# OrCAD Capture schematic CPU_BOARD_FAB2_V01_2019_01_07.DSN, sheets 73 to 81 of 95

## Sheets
73 063 SNOWFLAKE_3: size B
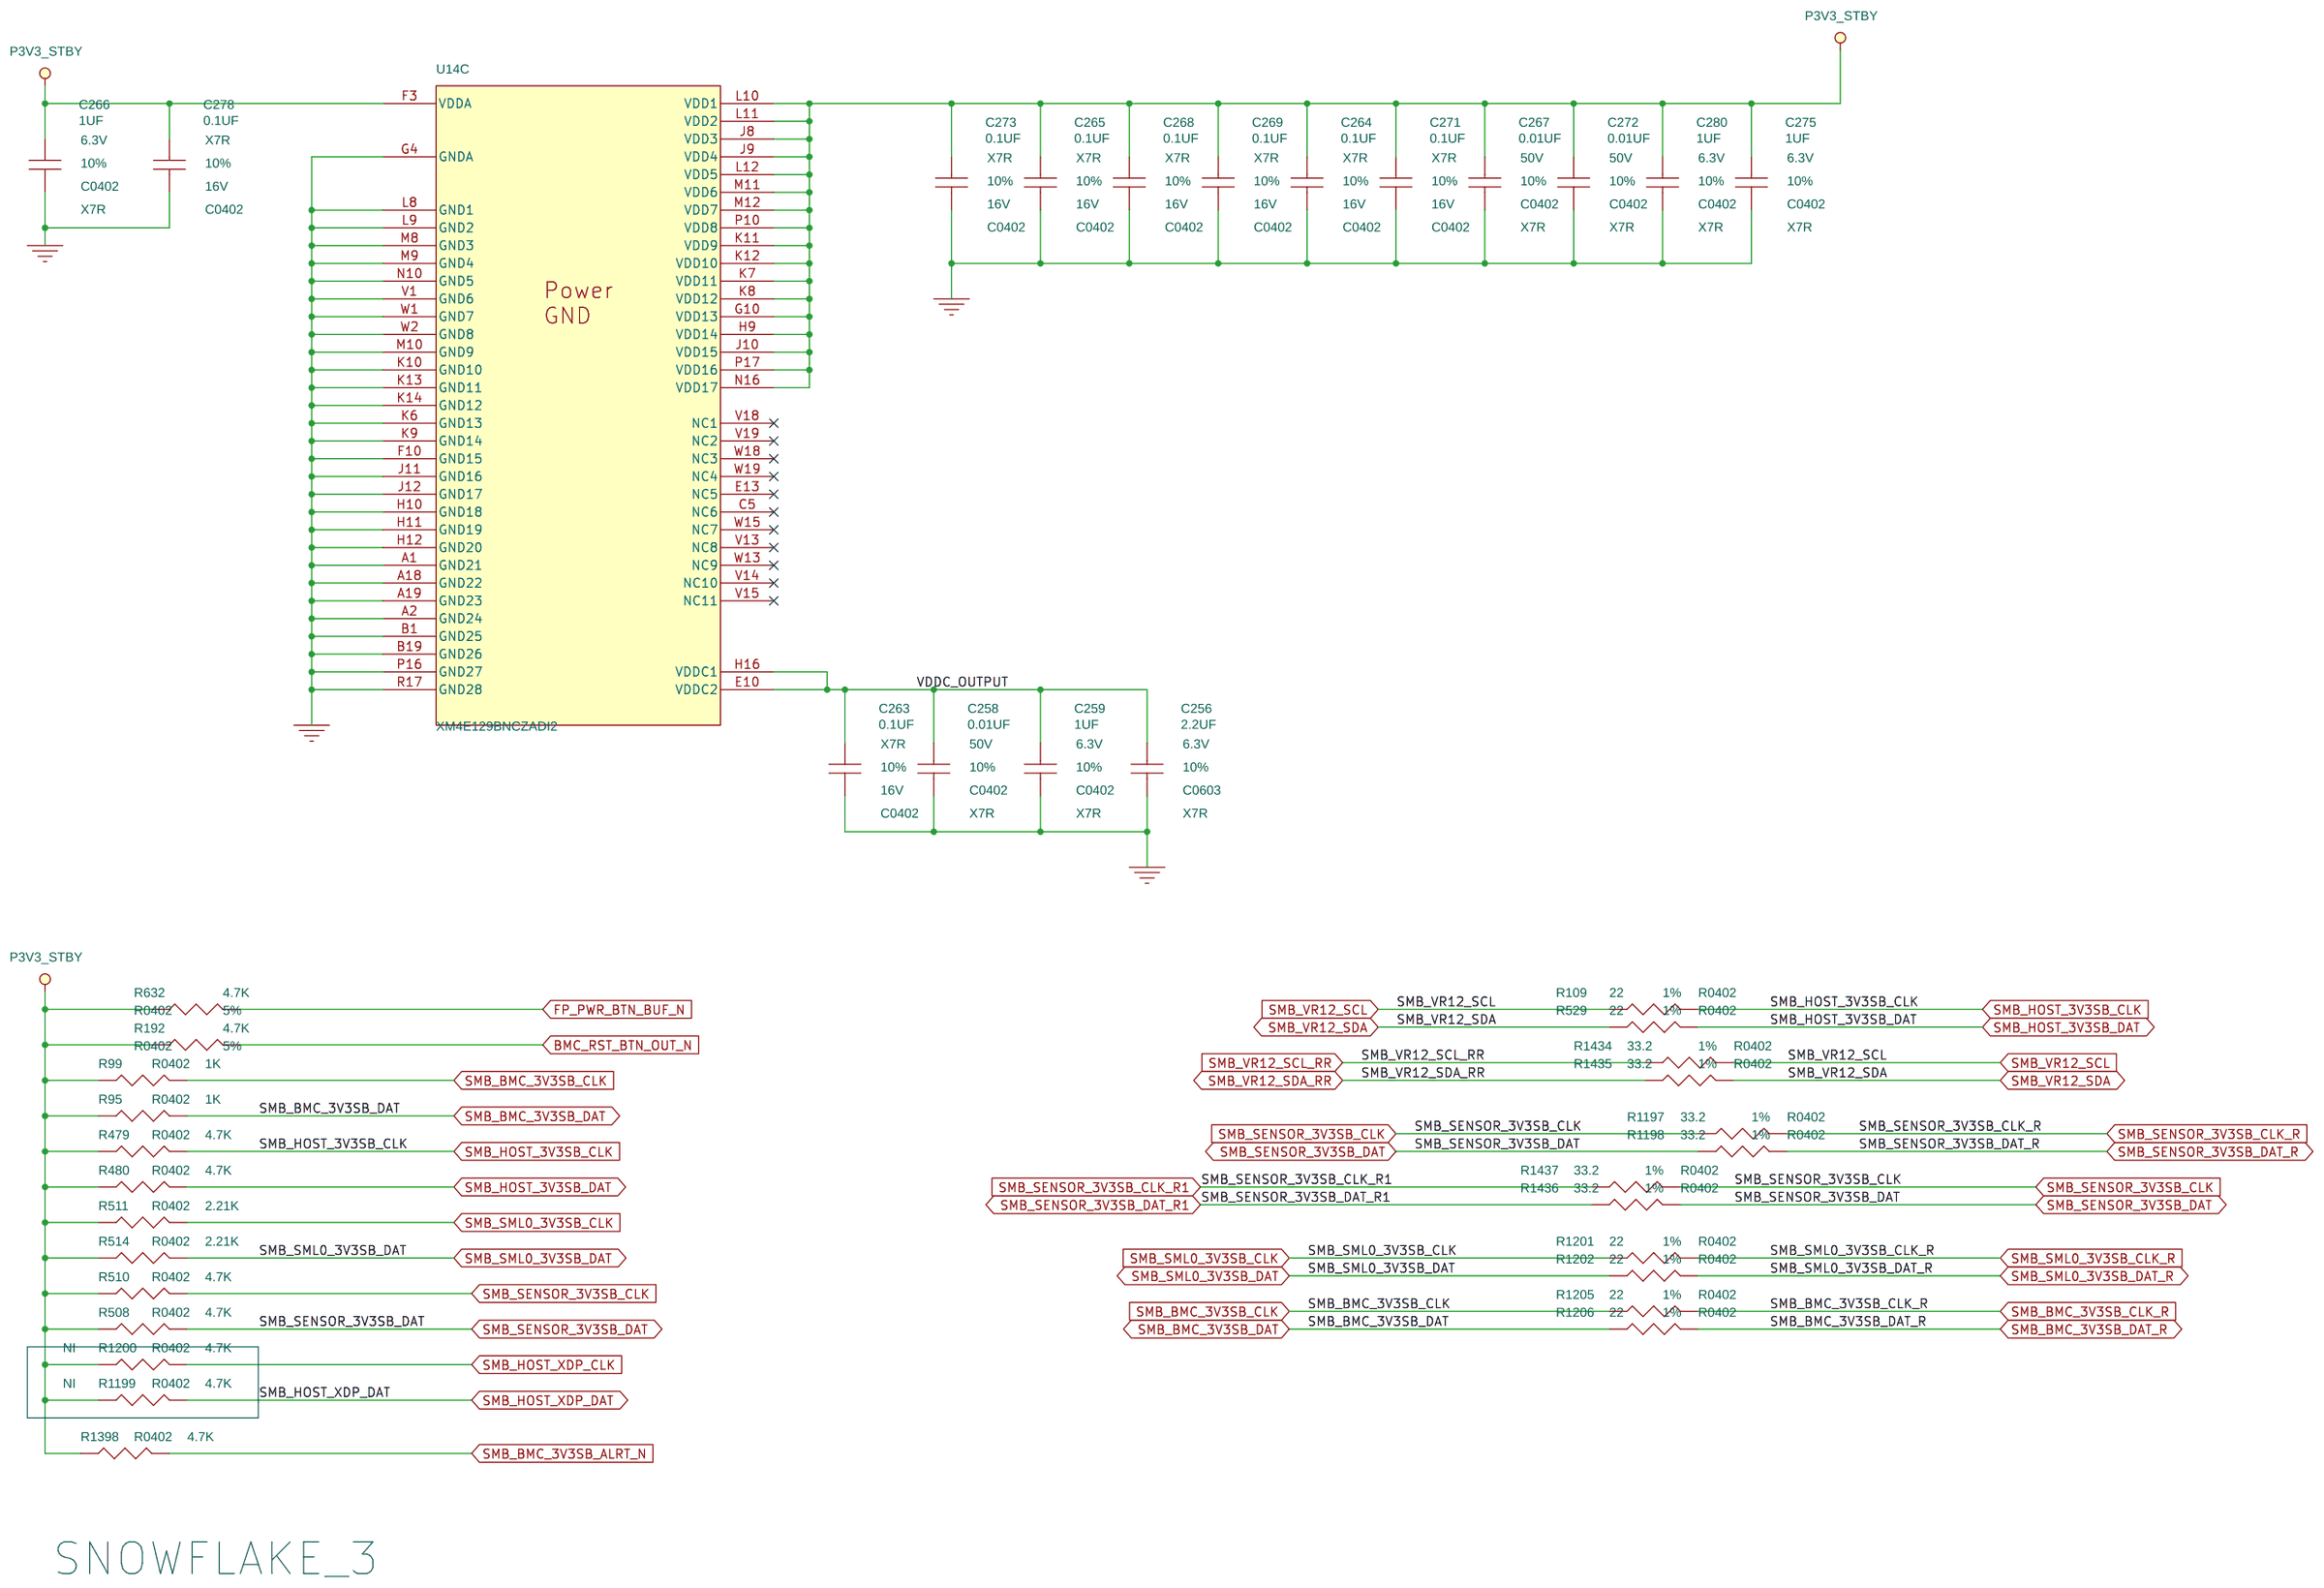
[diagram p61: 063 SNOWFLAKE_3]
74 064 VOLTAGE MONITOR: size B
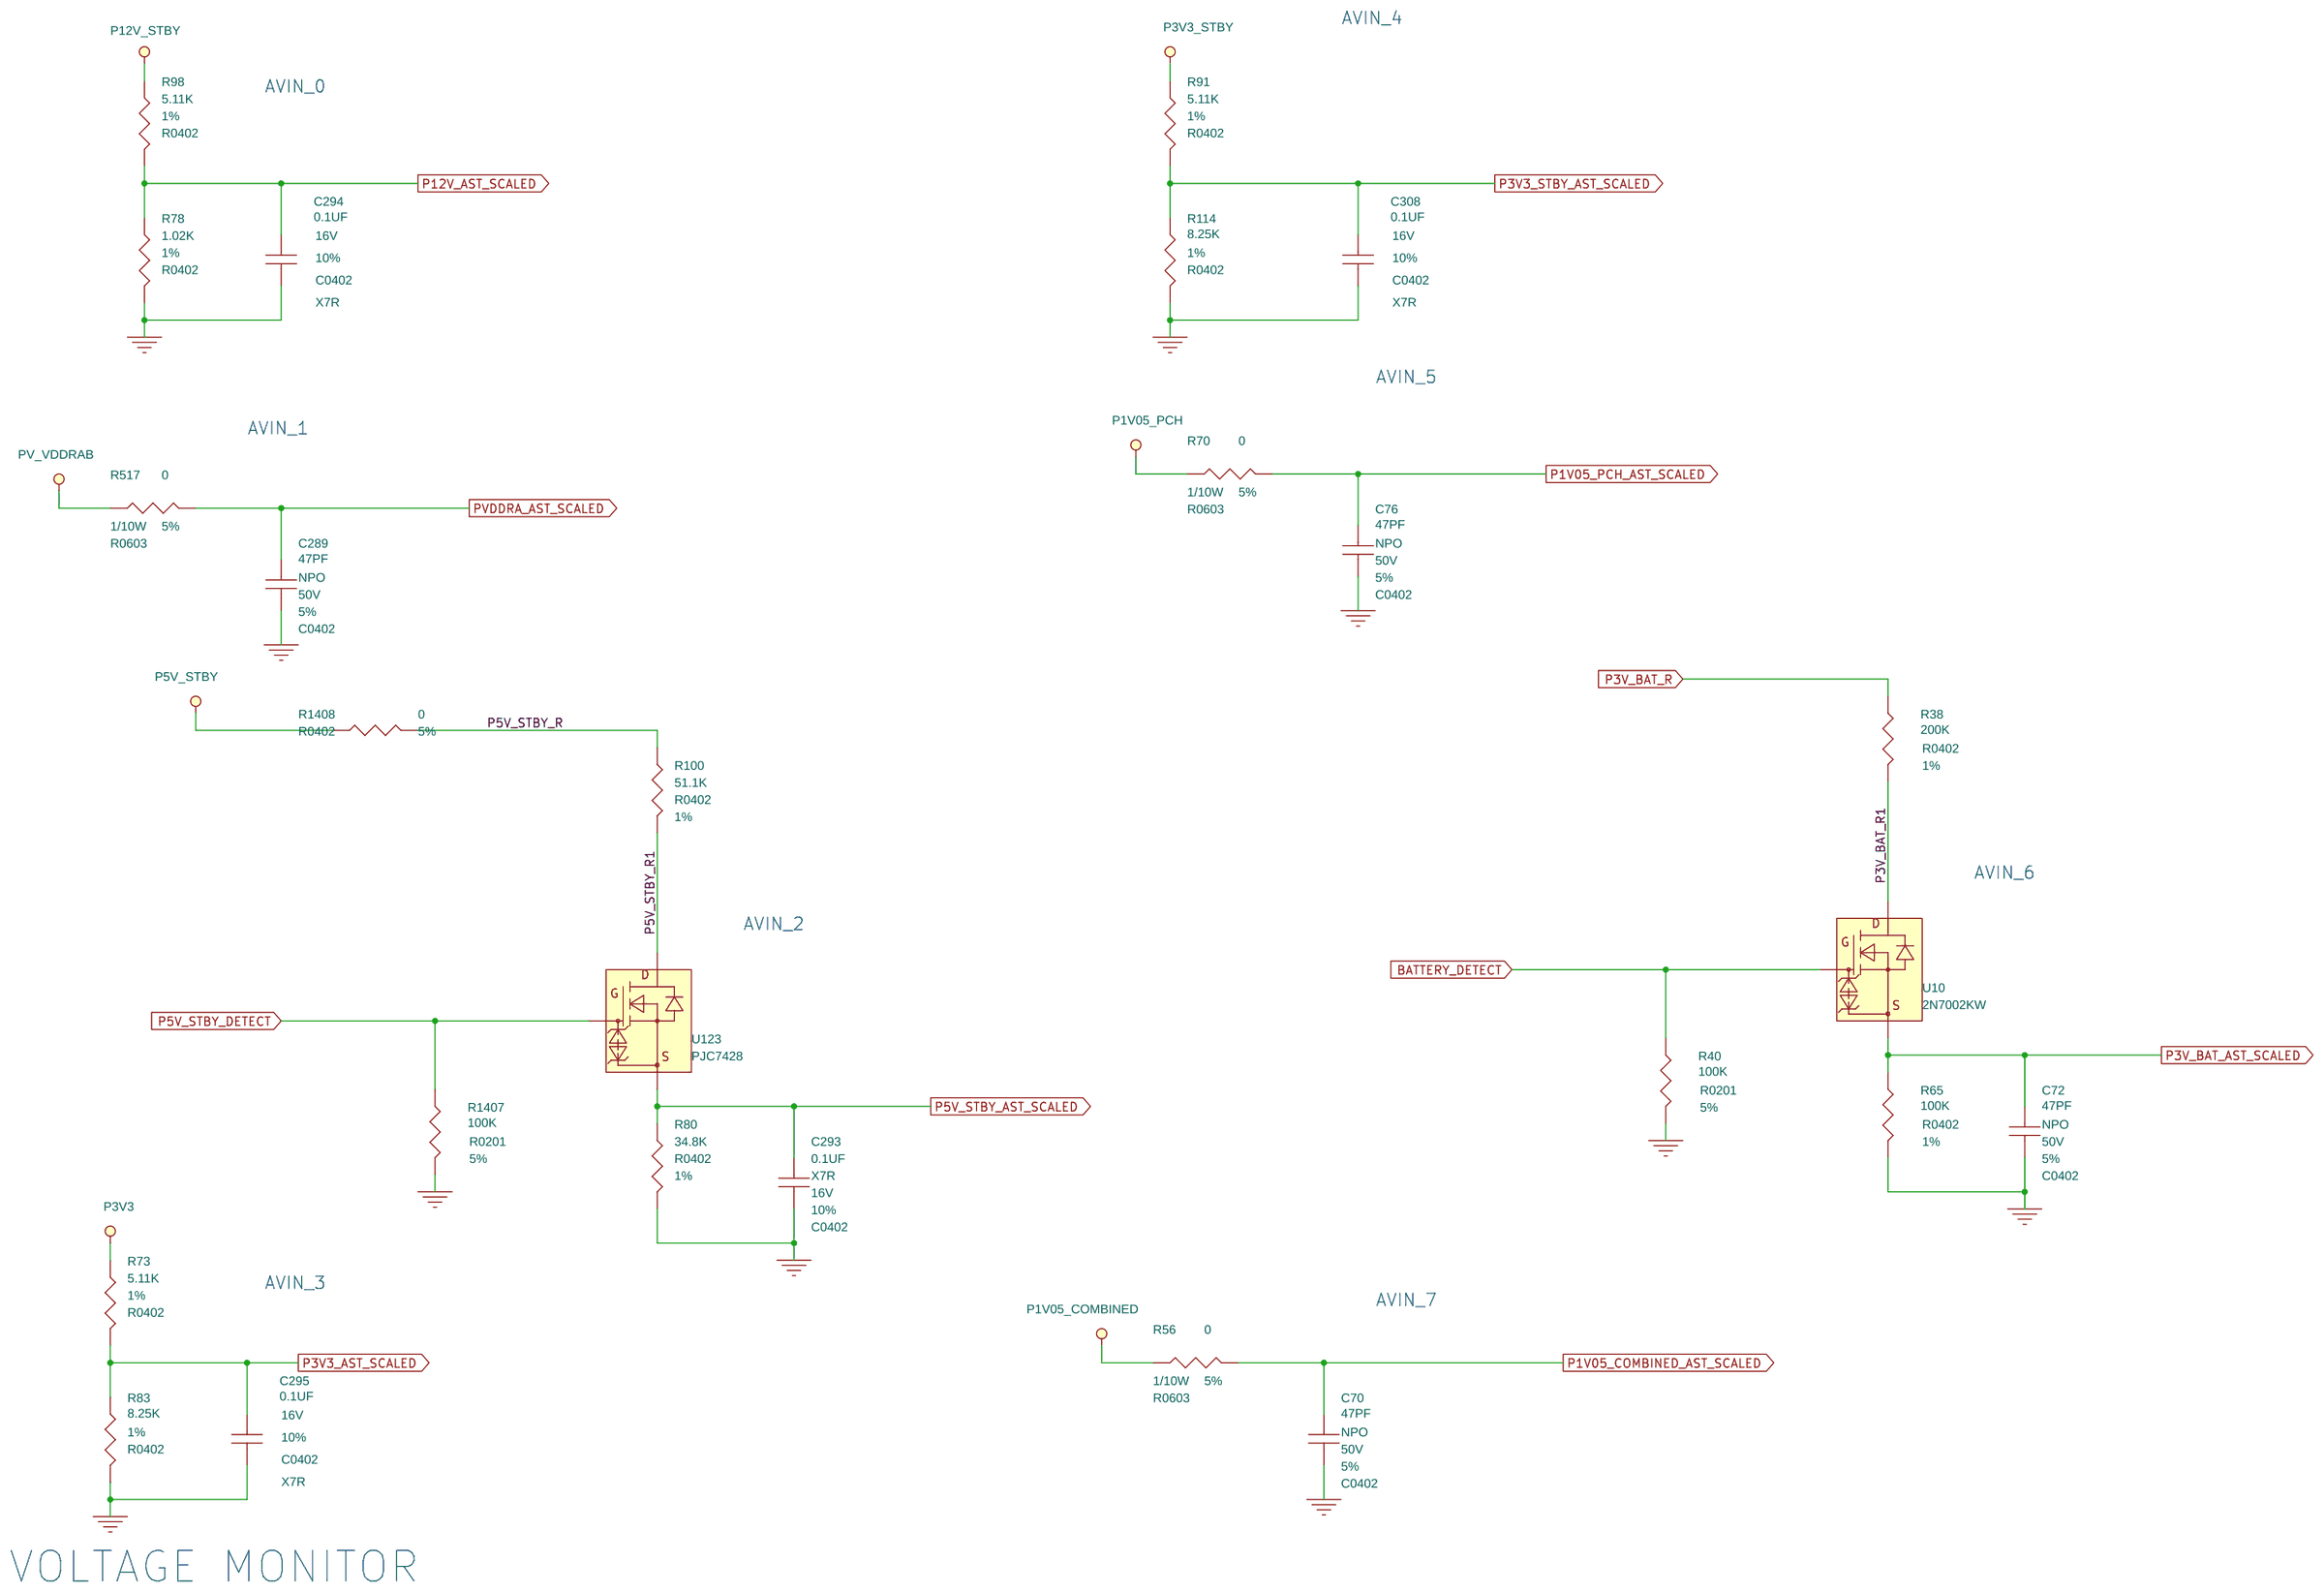
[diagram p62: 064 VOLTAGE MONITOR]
75 065 SMBUS ISOLATOR: size B
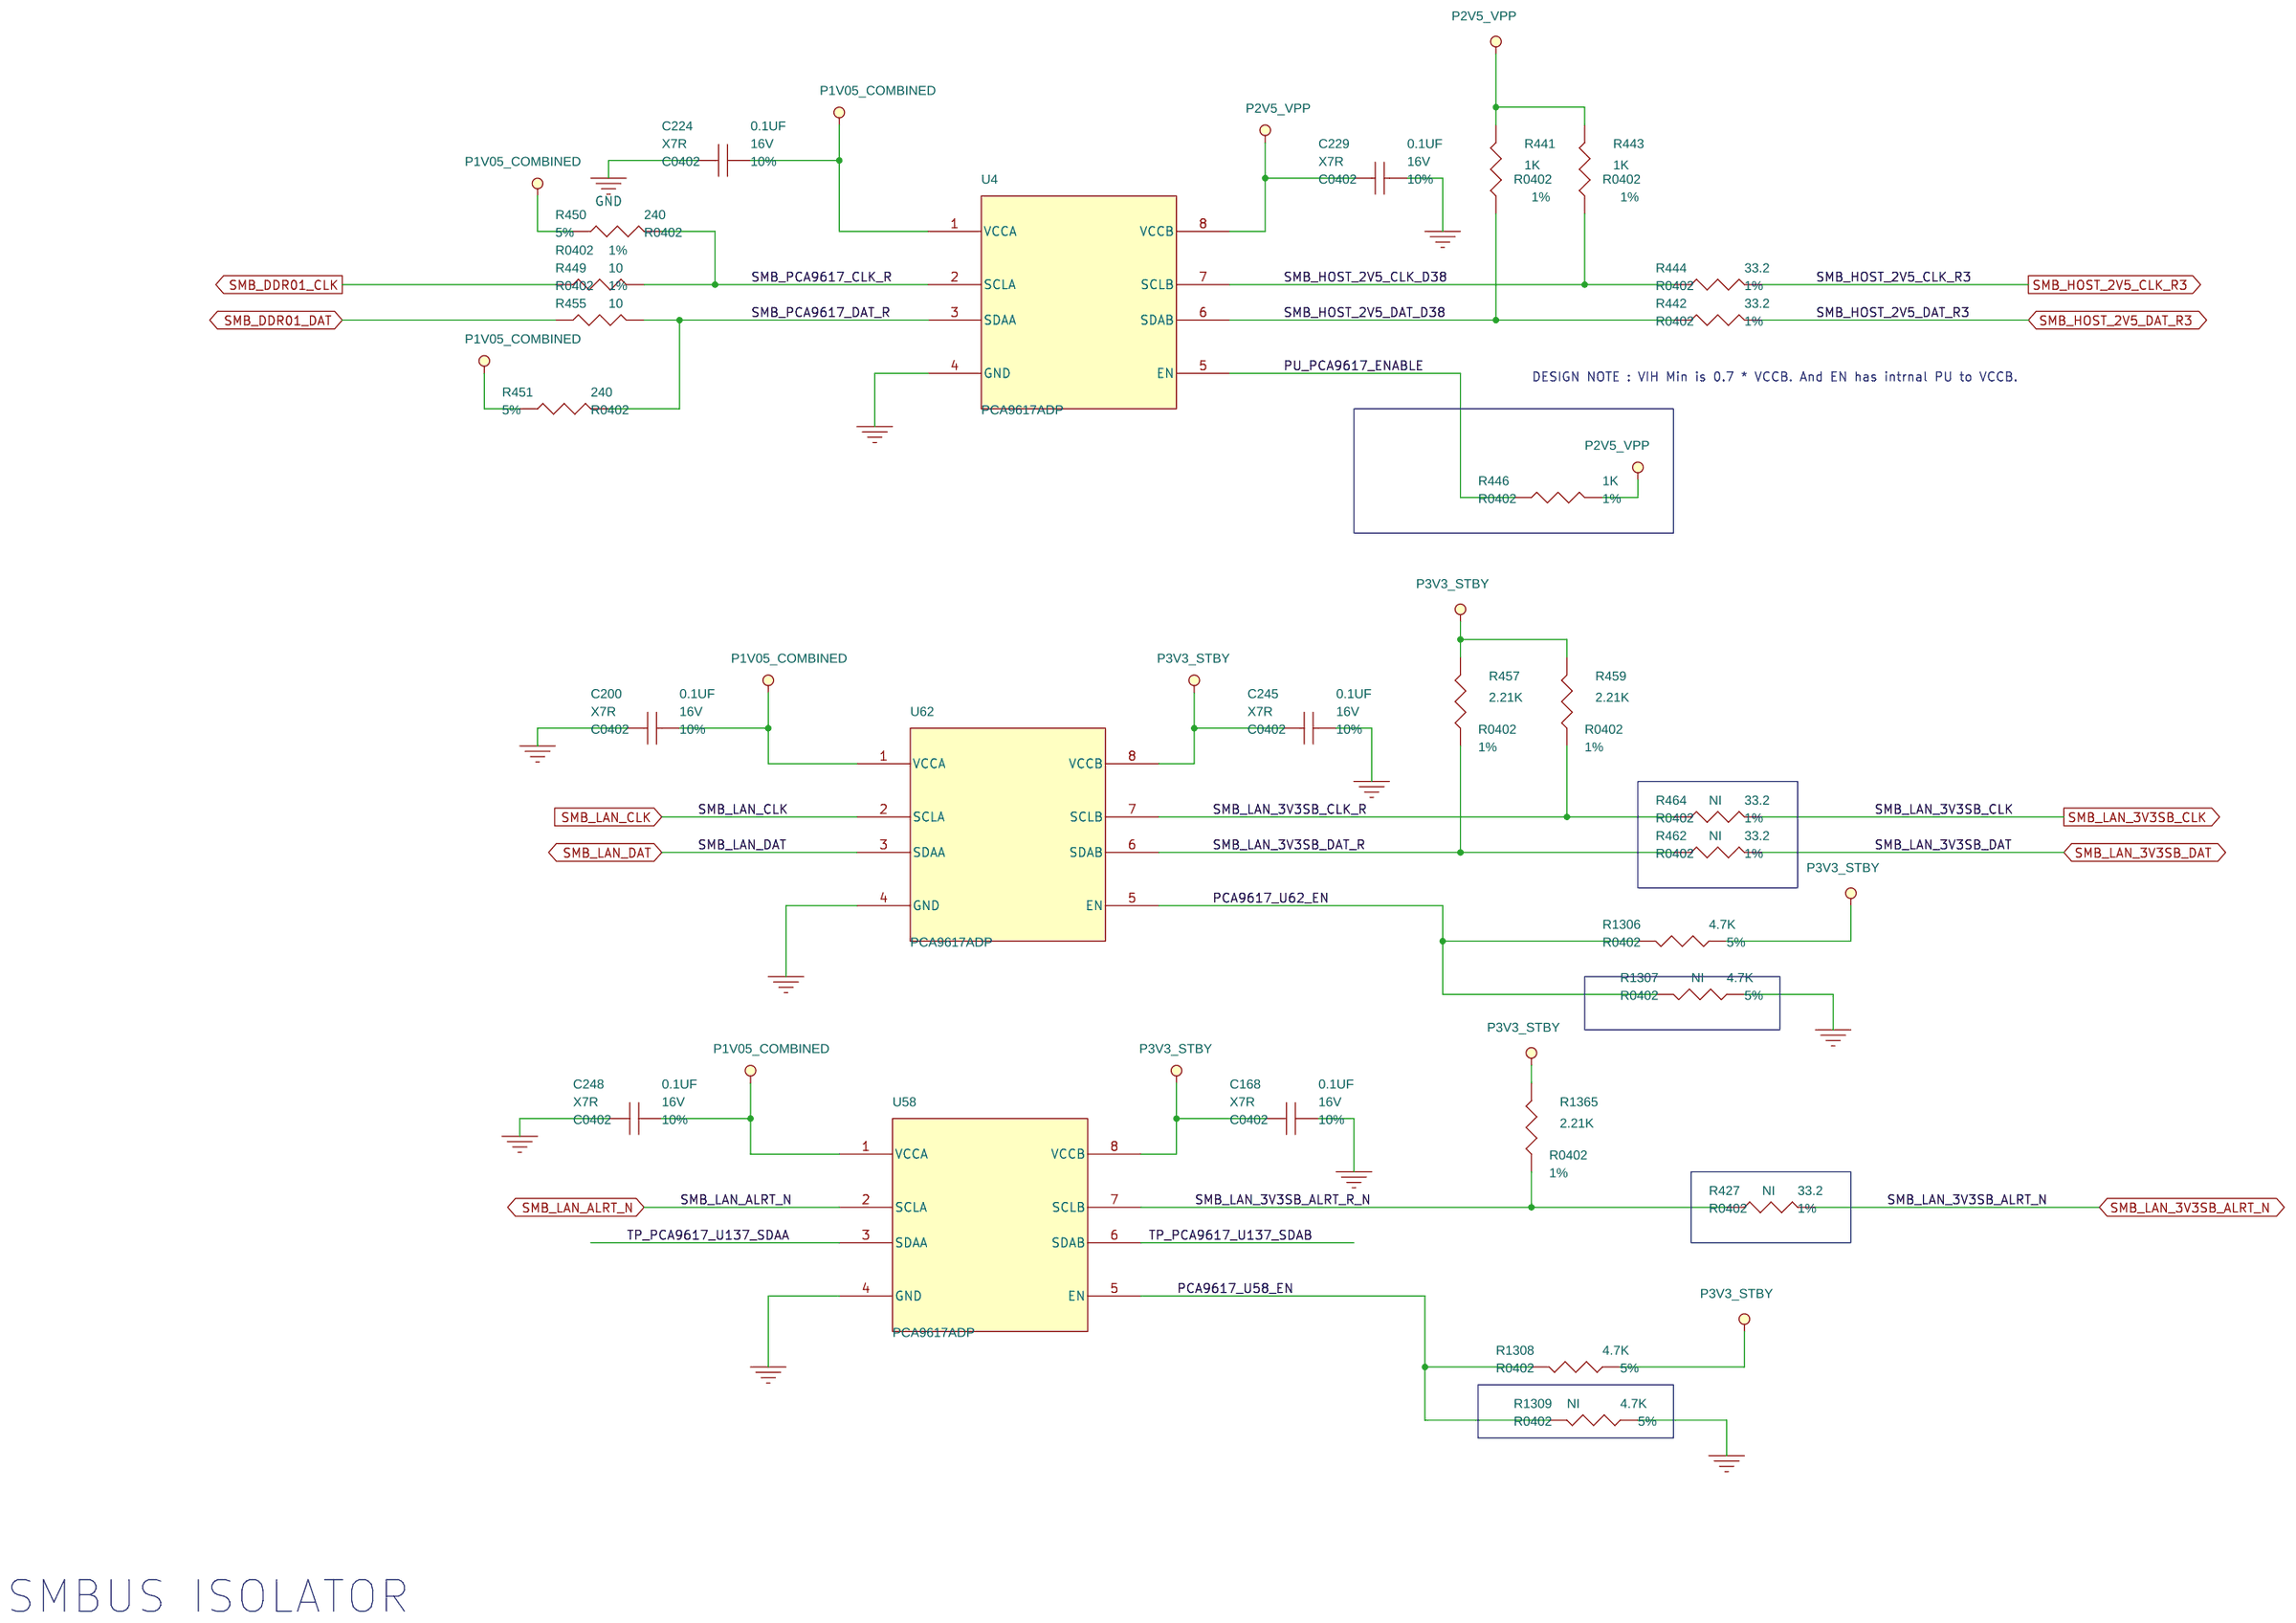
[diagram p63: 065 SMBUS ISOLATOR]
76 069 DELTA-L AND TDR_3: size B
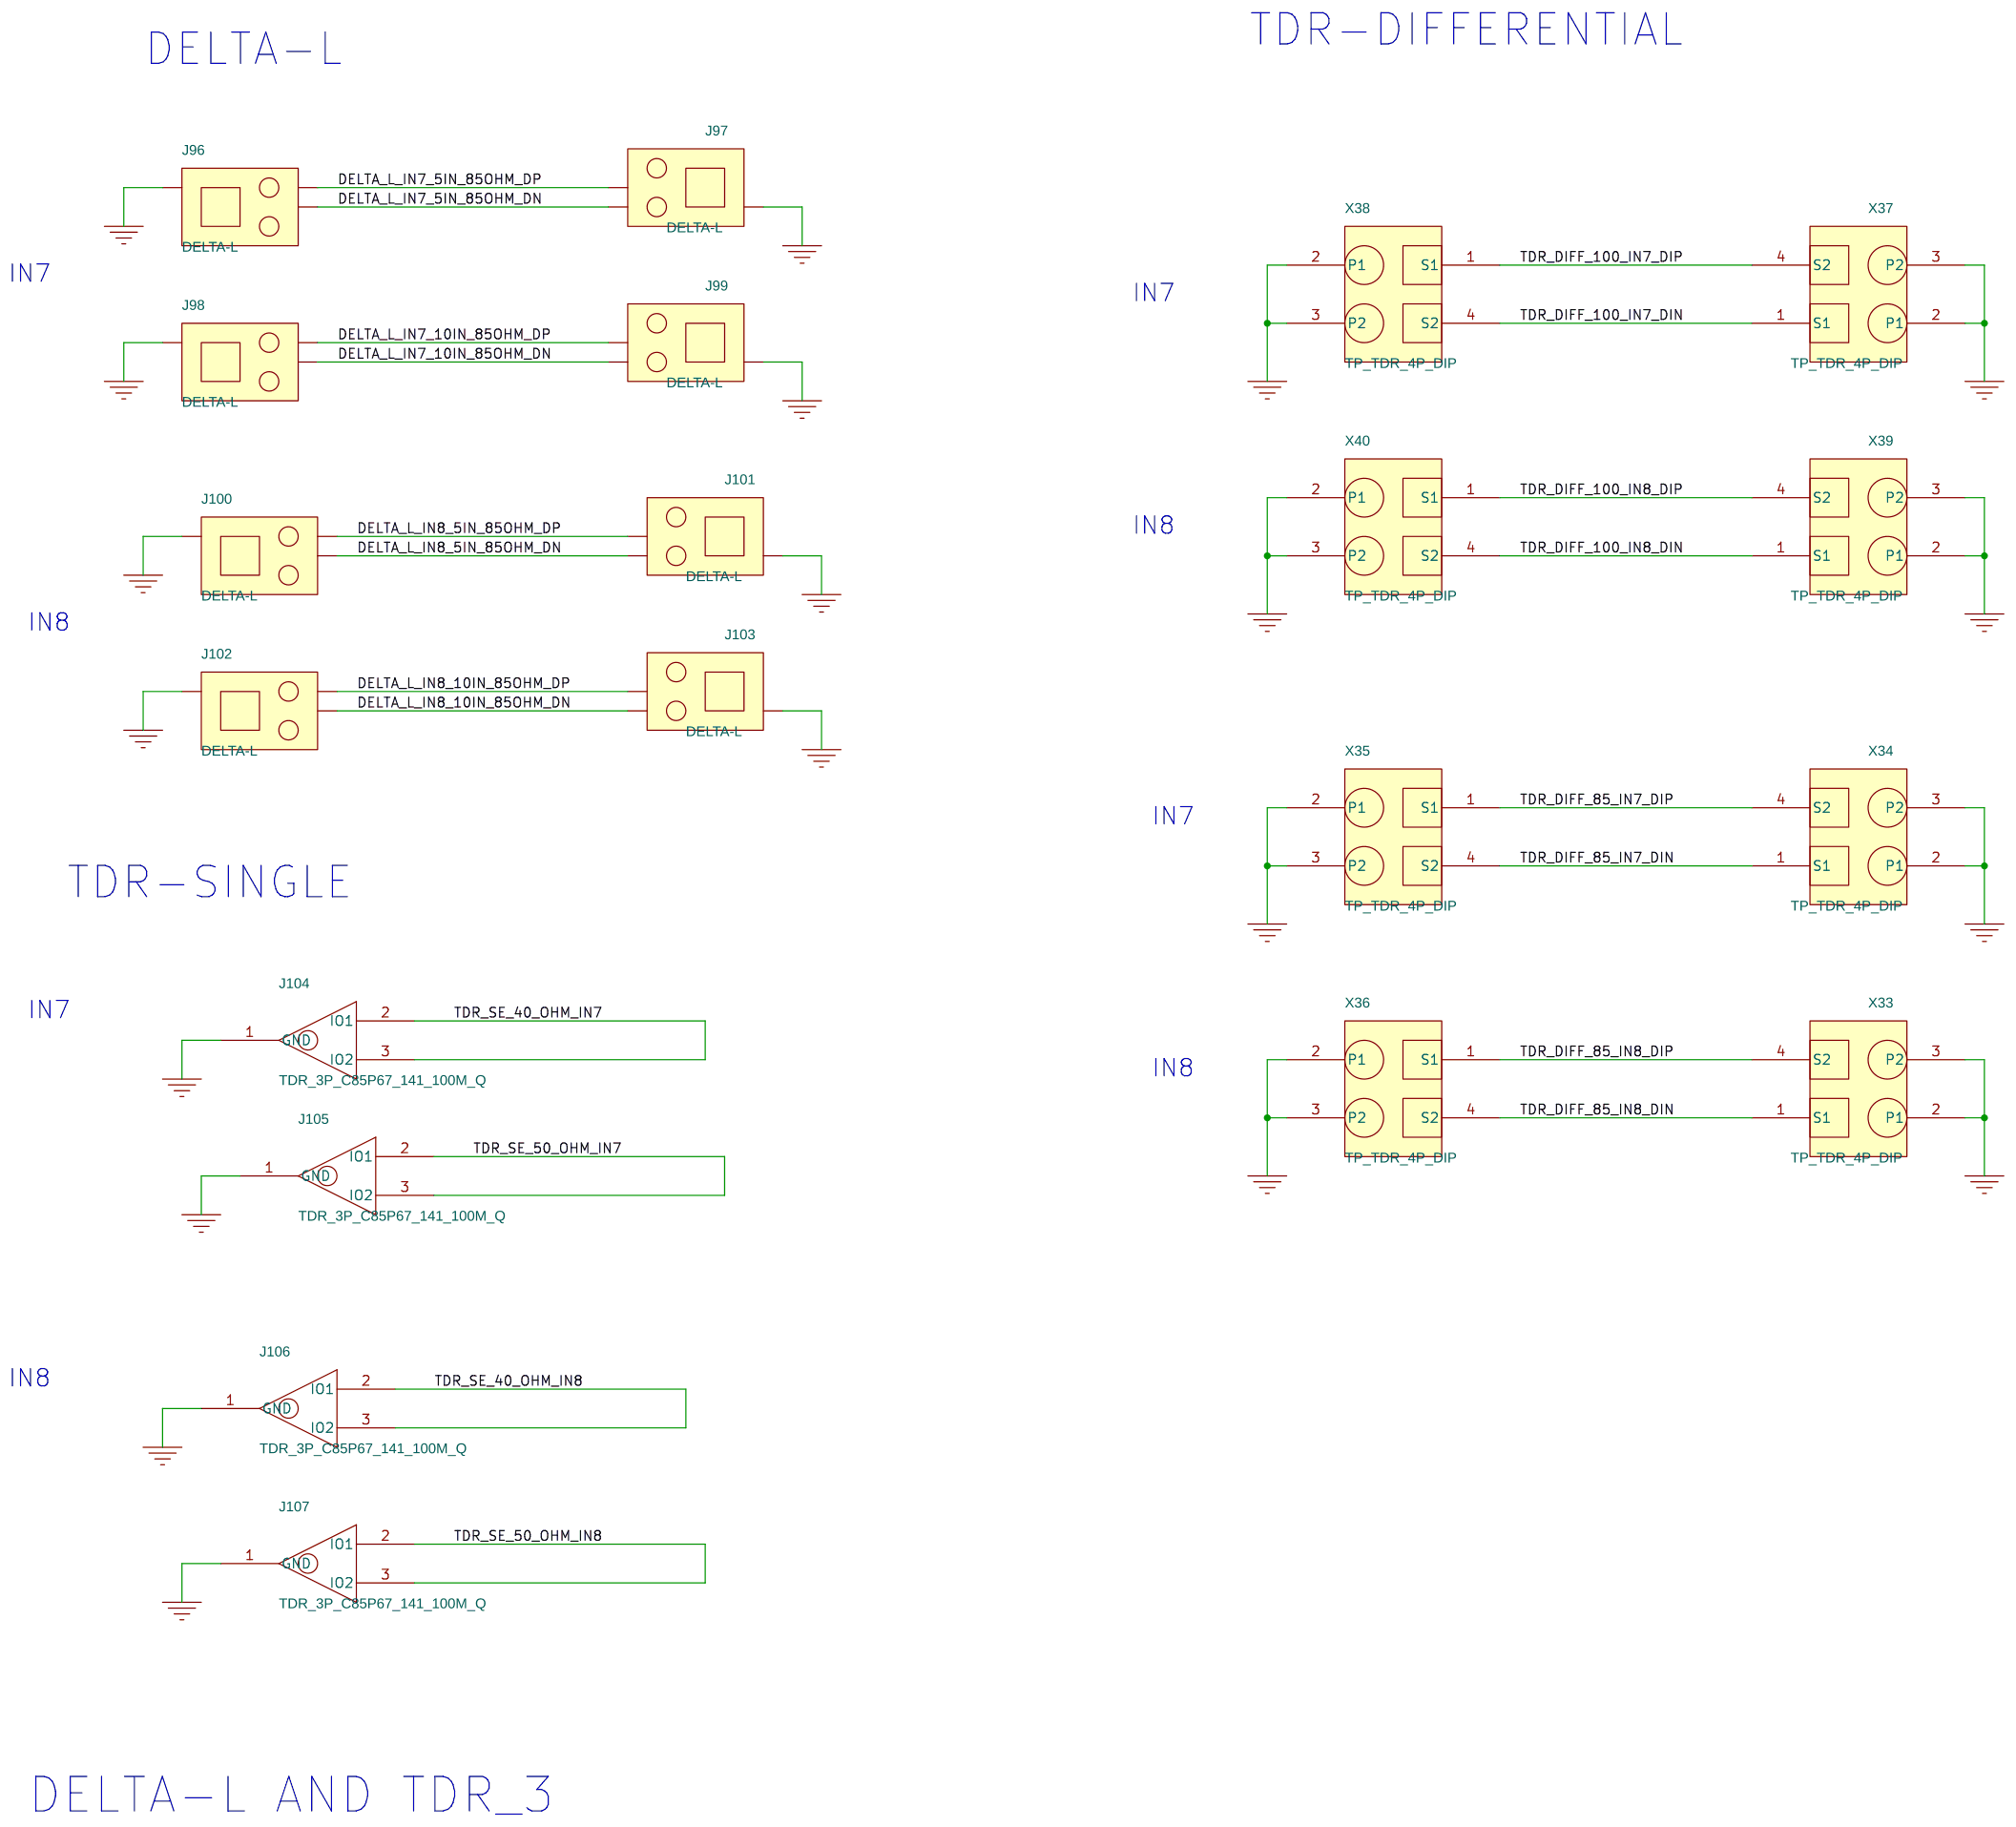
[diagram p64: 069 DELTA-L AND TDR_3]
77 066 PWR_ PORT 80 LED: size B
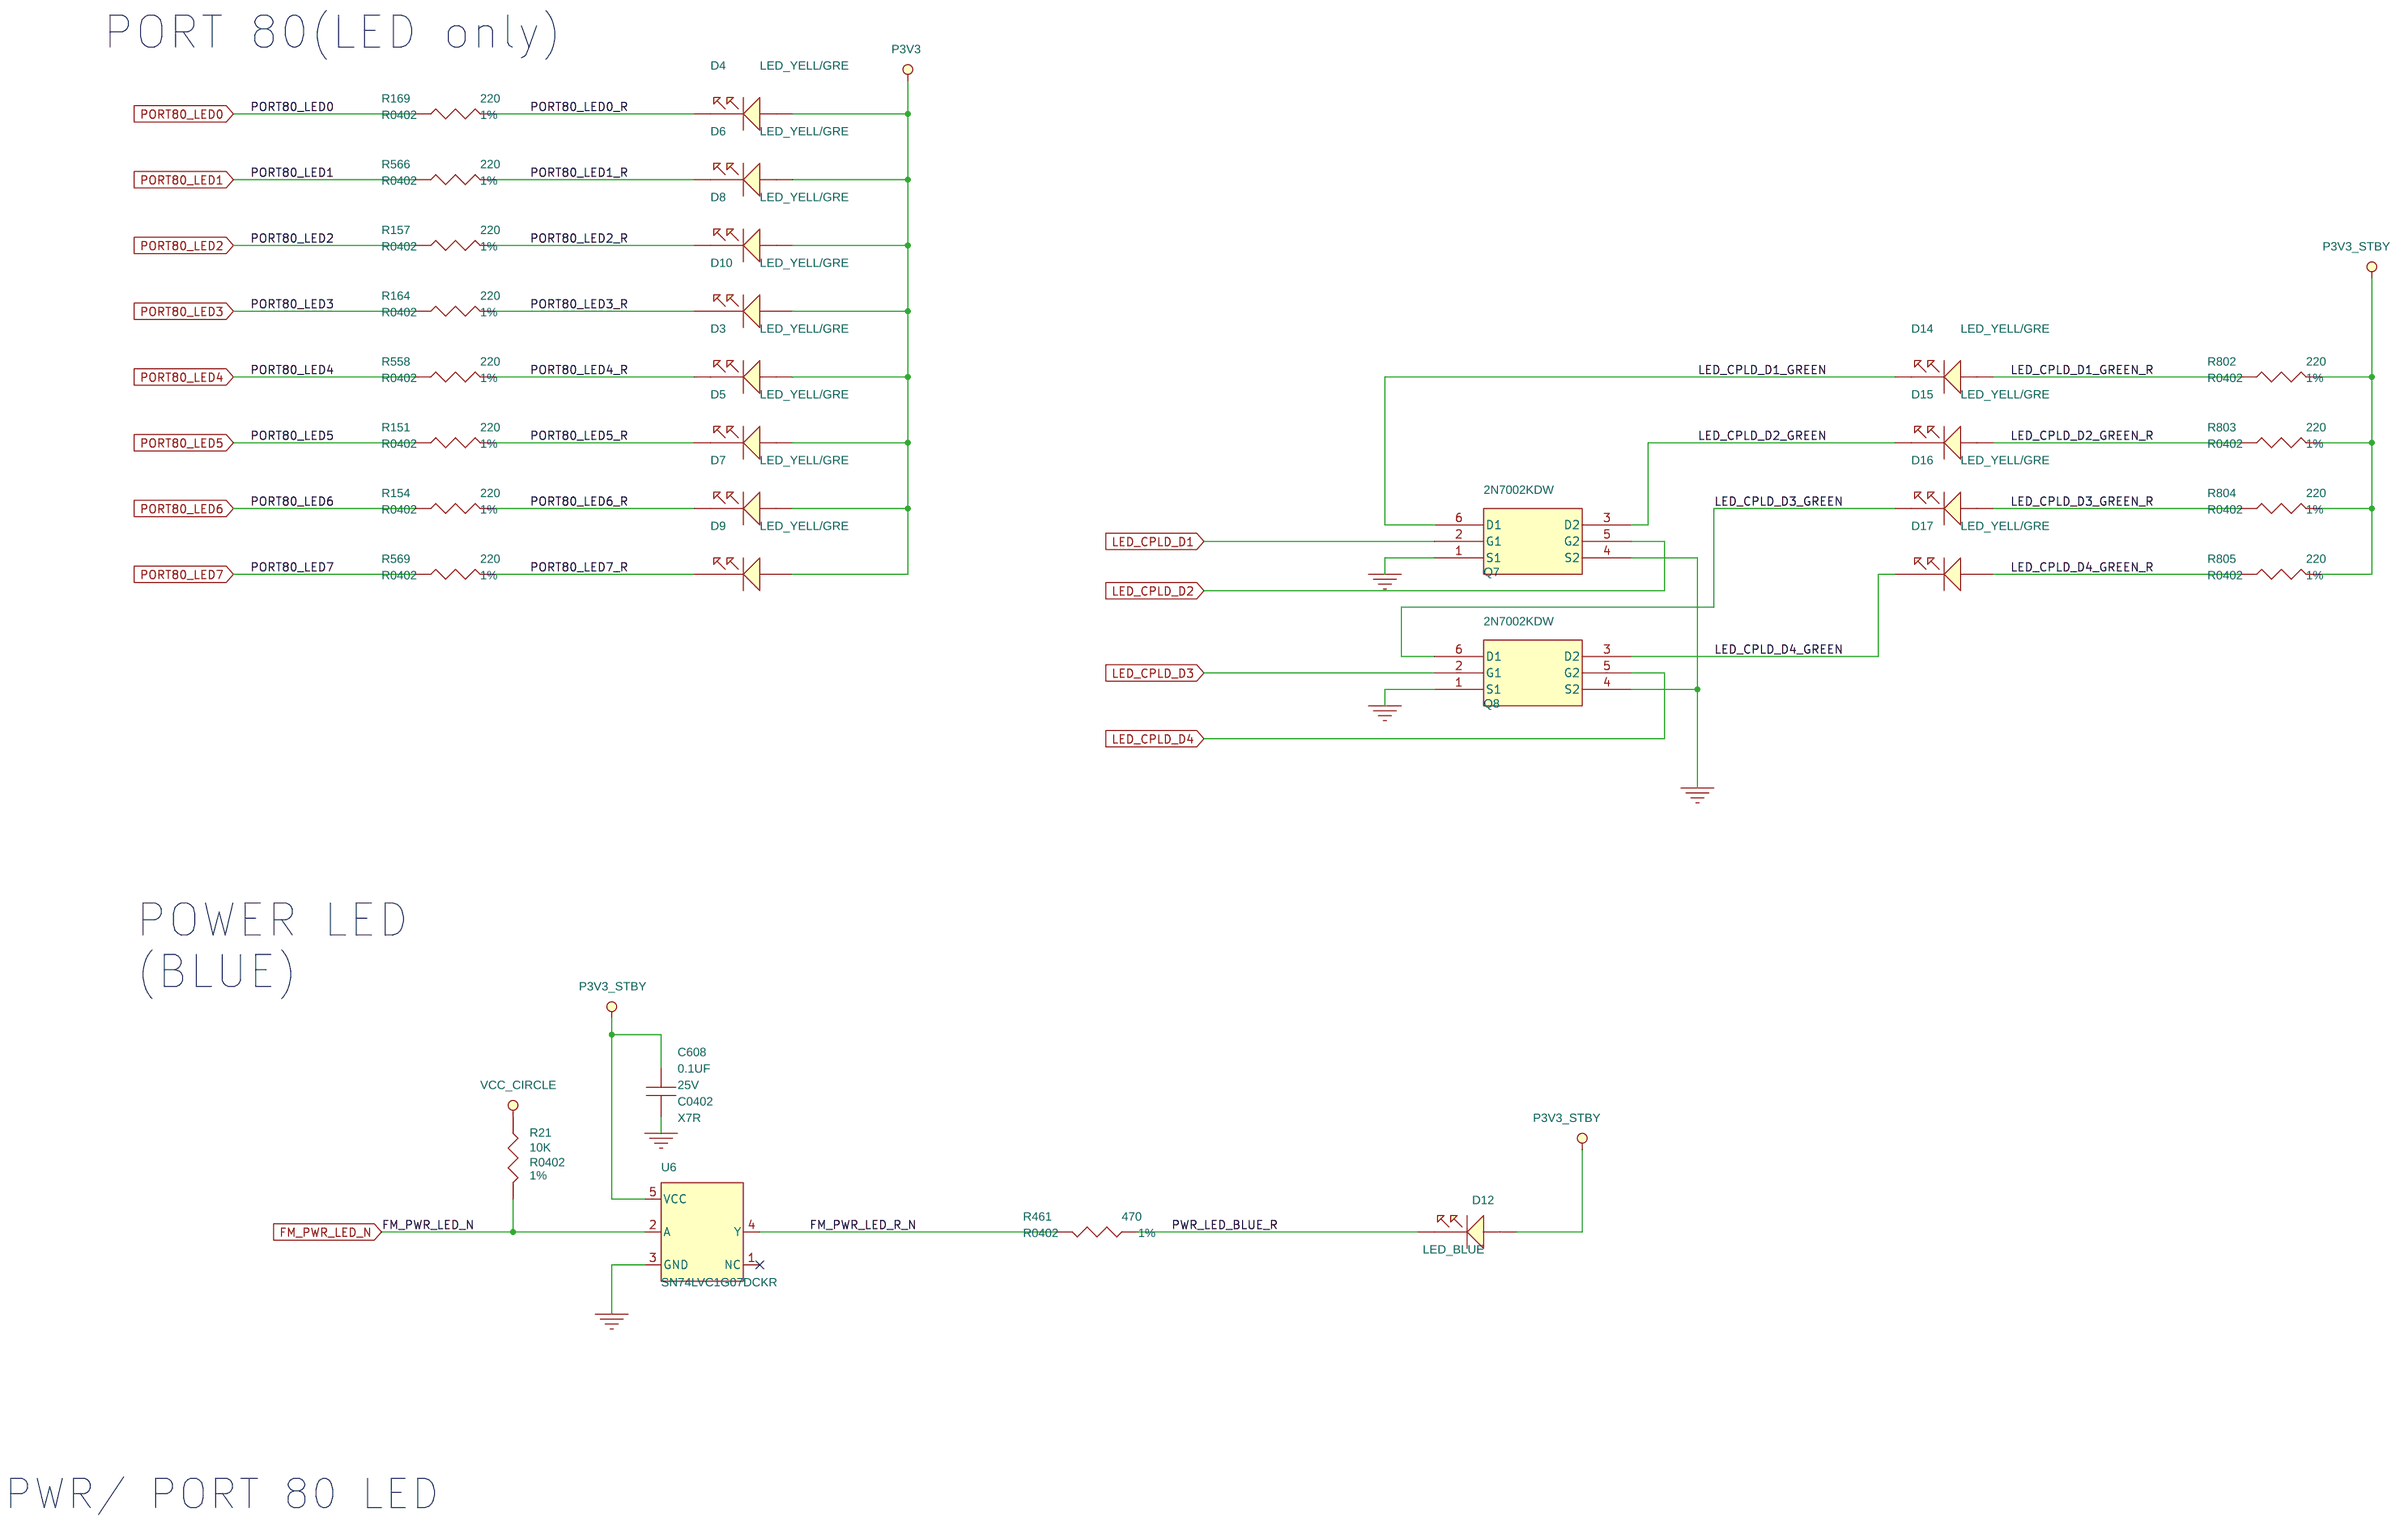
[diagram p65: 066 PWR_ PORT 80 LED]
78 067 DELTA-L AND TDR_1: size B
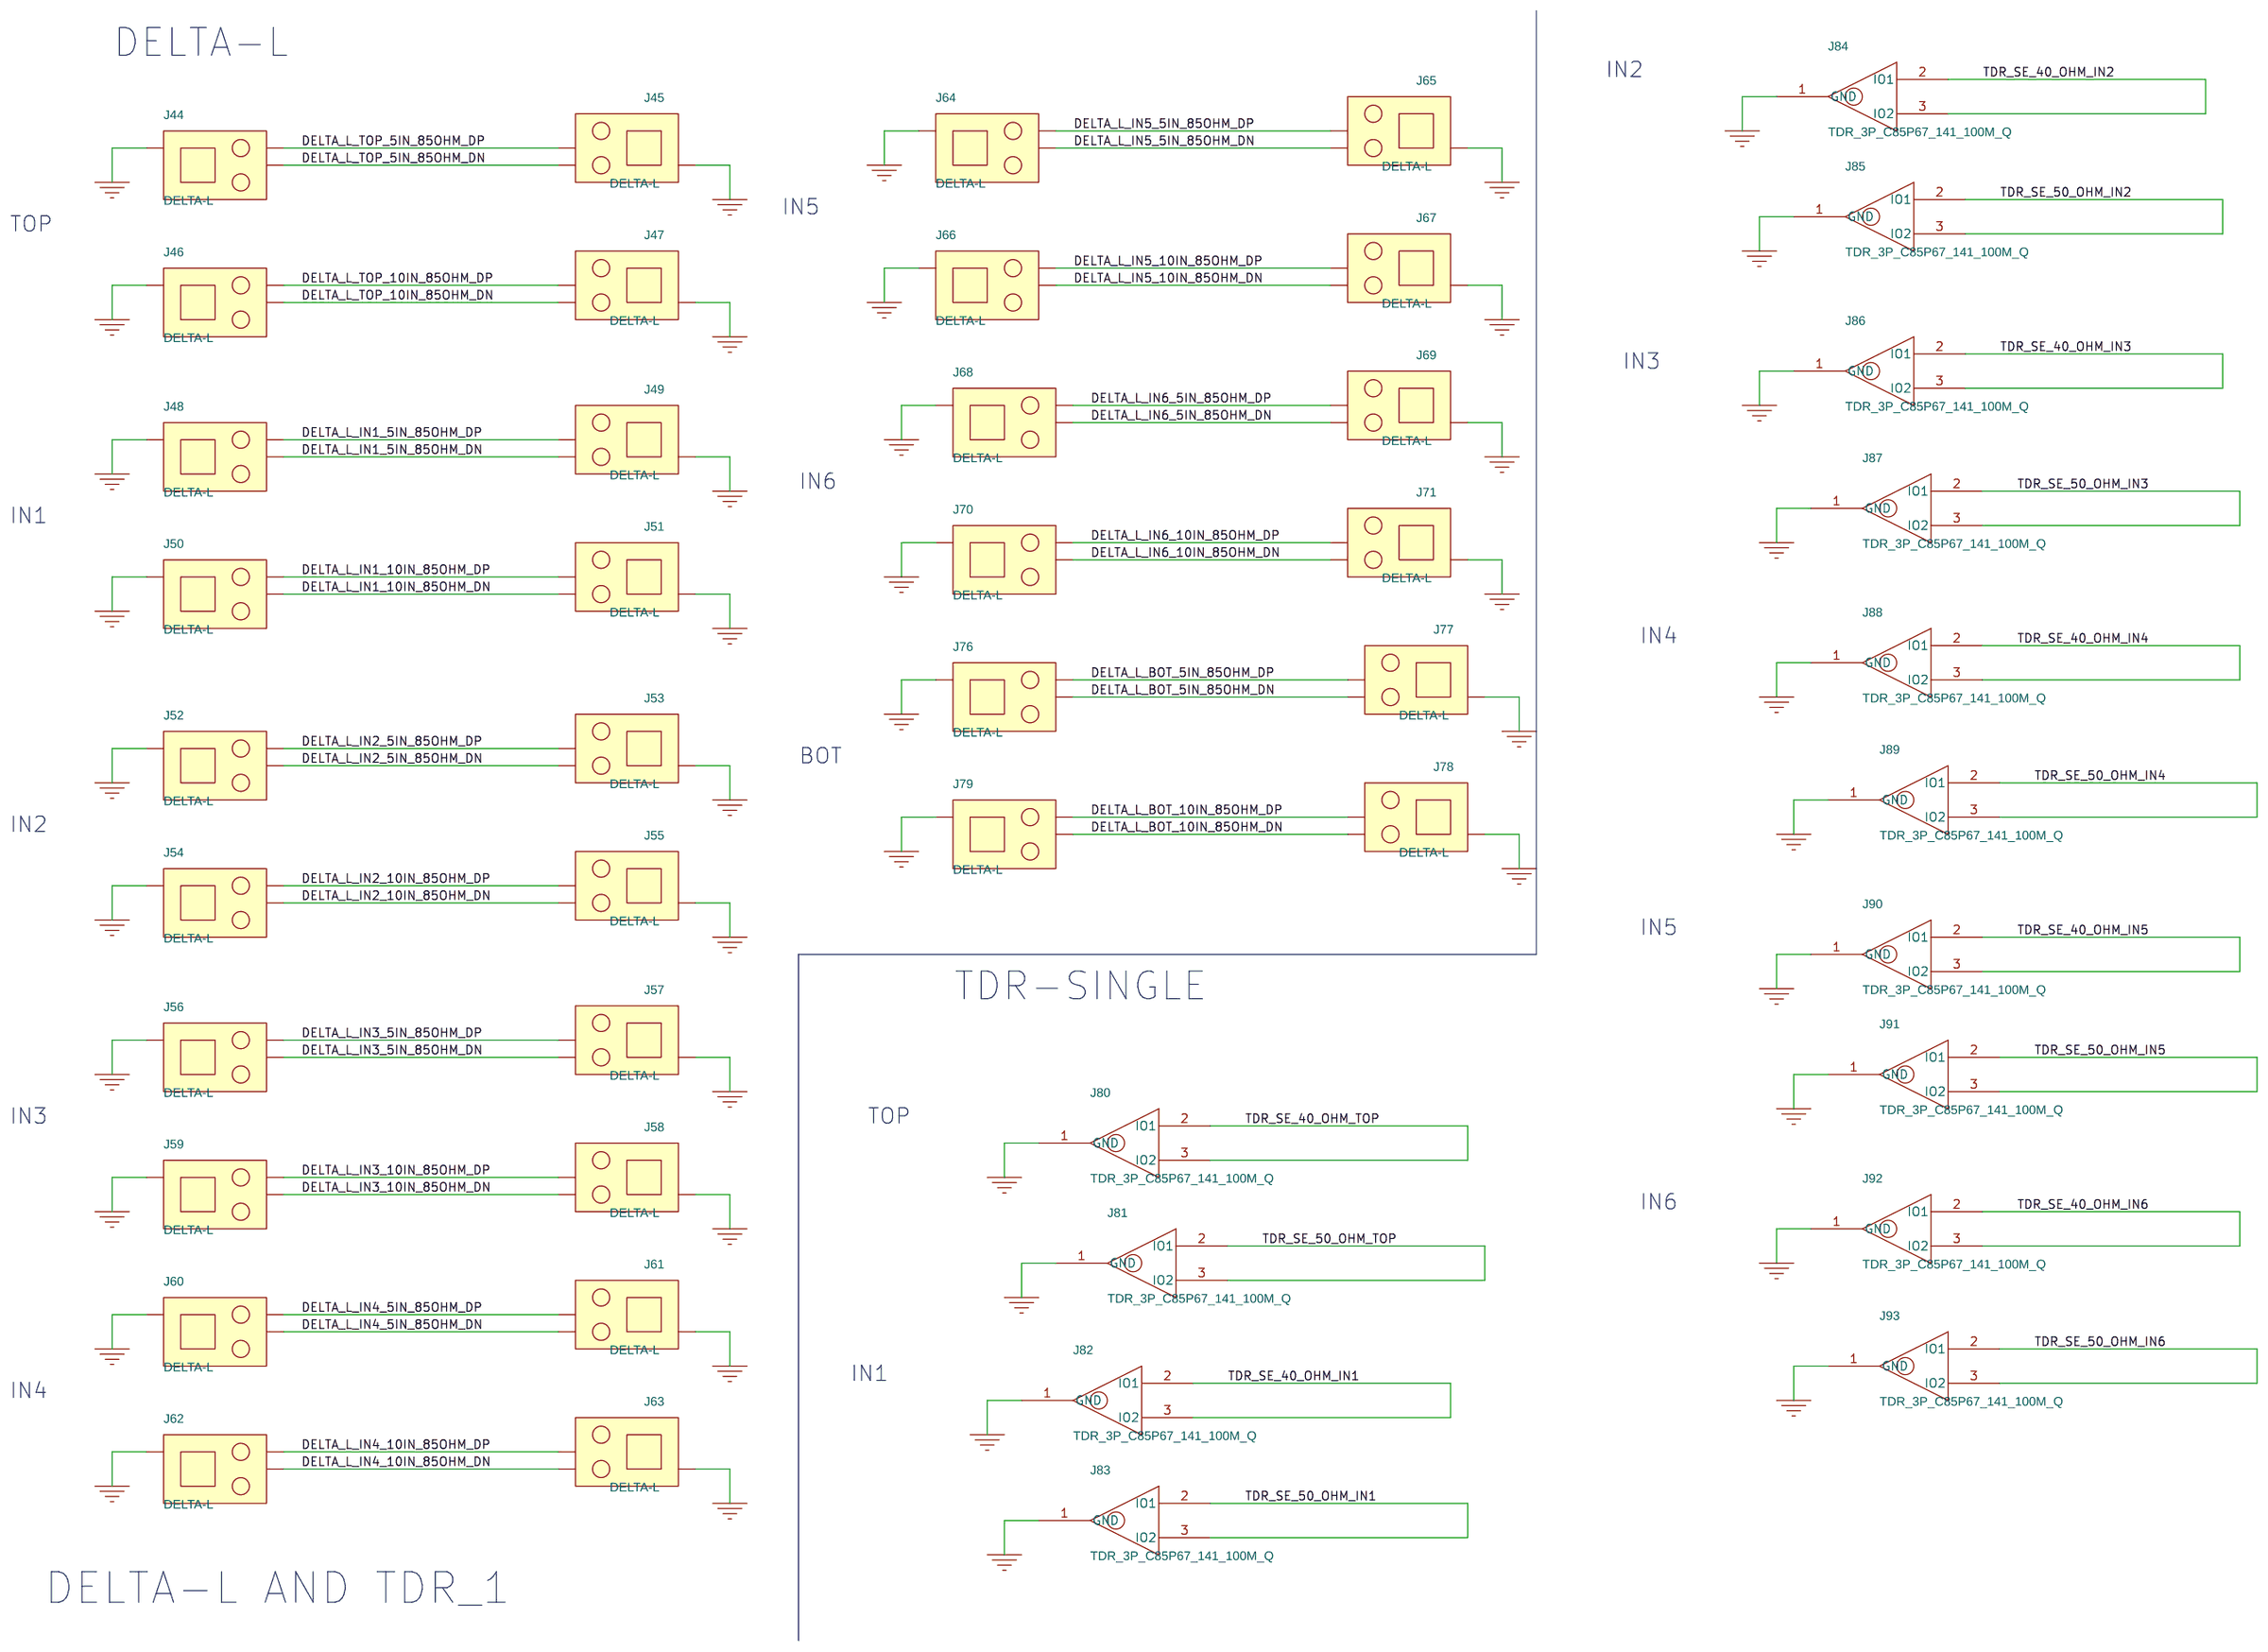
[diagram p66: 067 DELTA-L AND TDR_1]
79 022 BDX-DE 10GBE LAN_2: size B
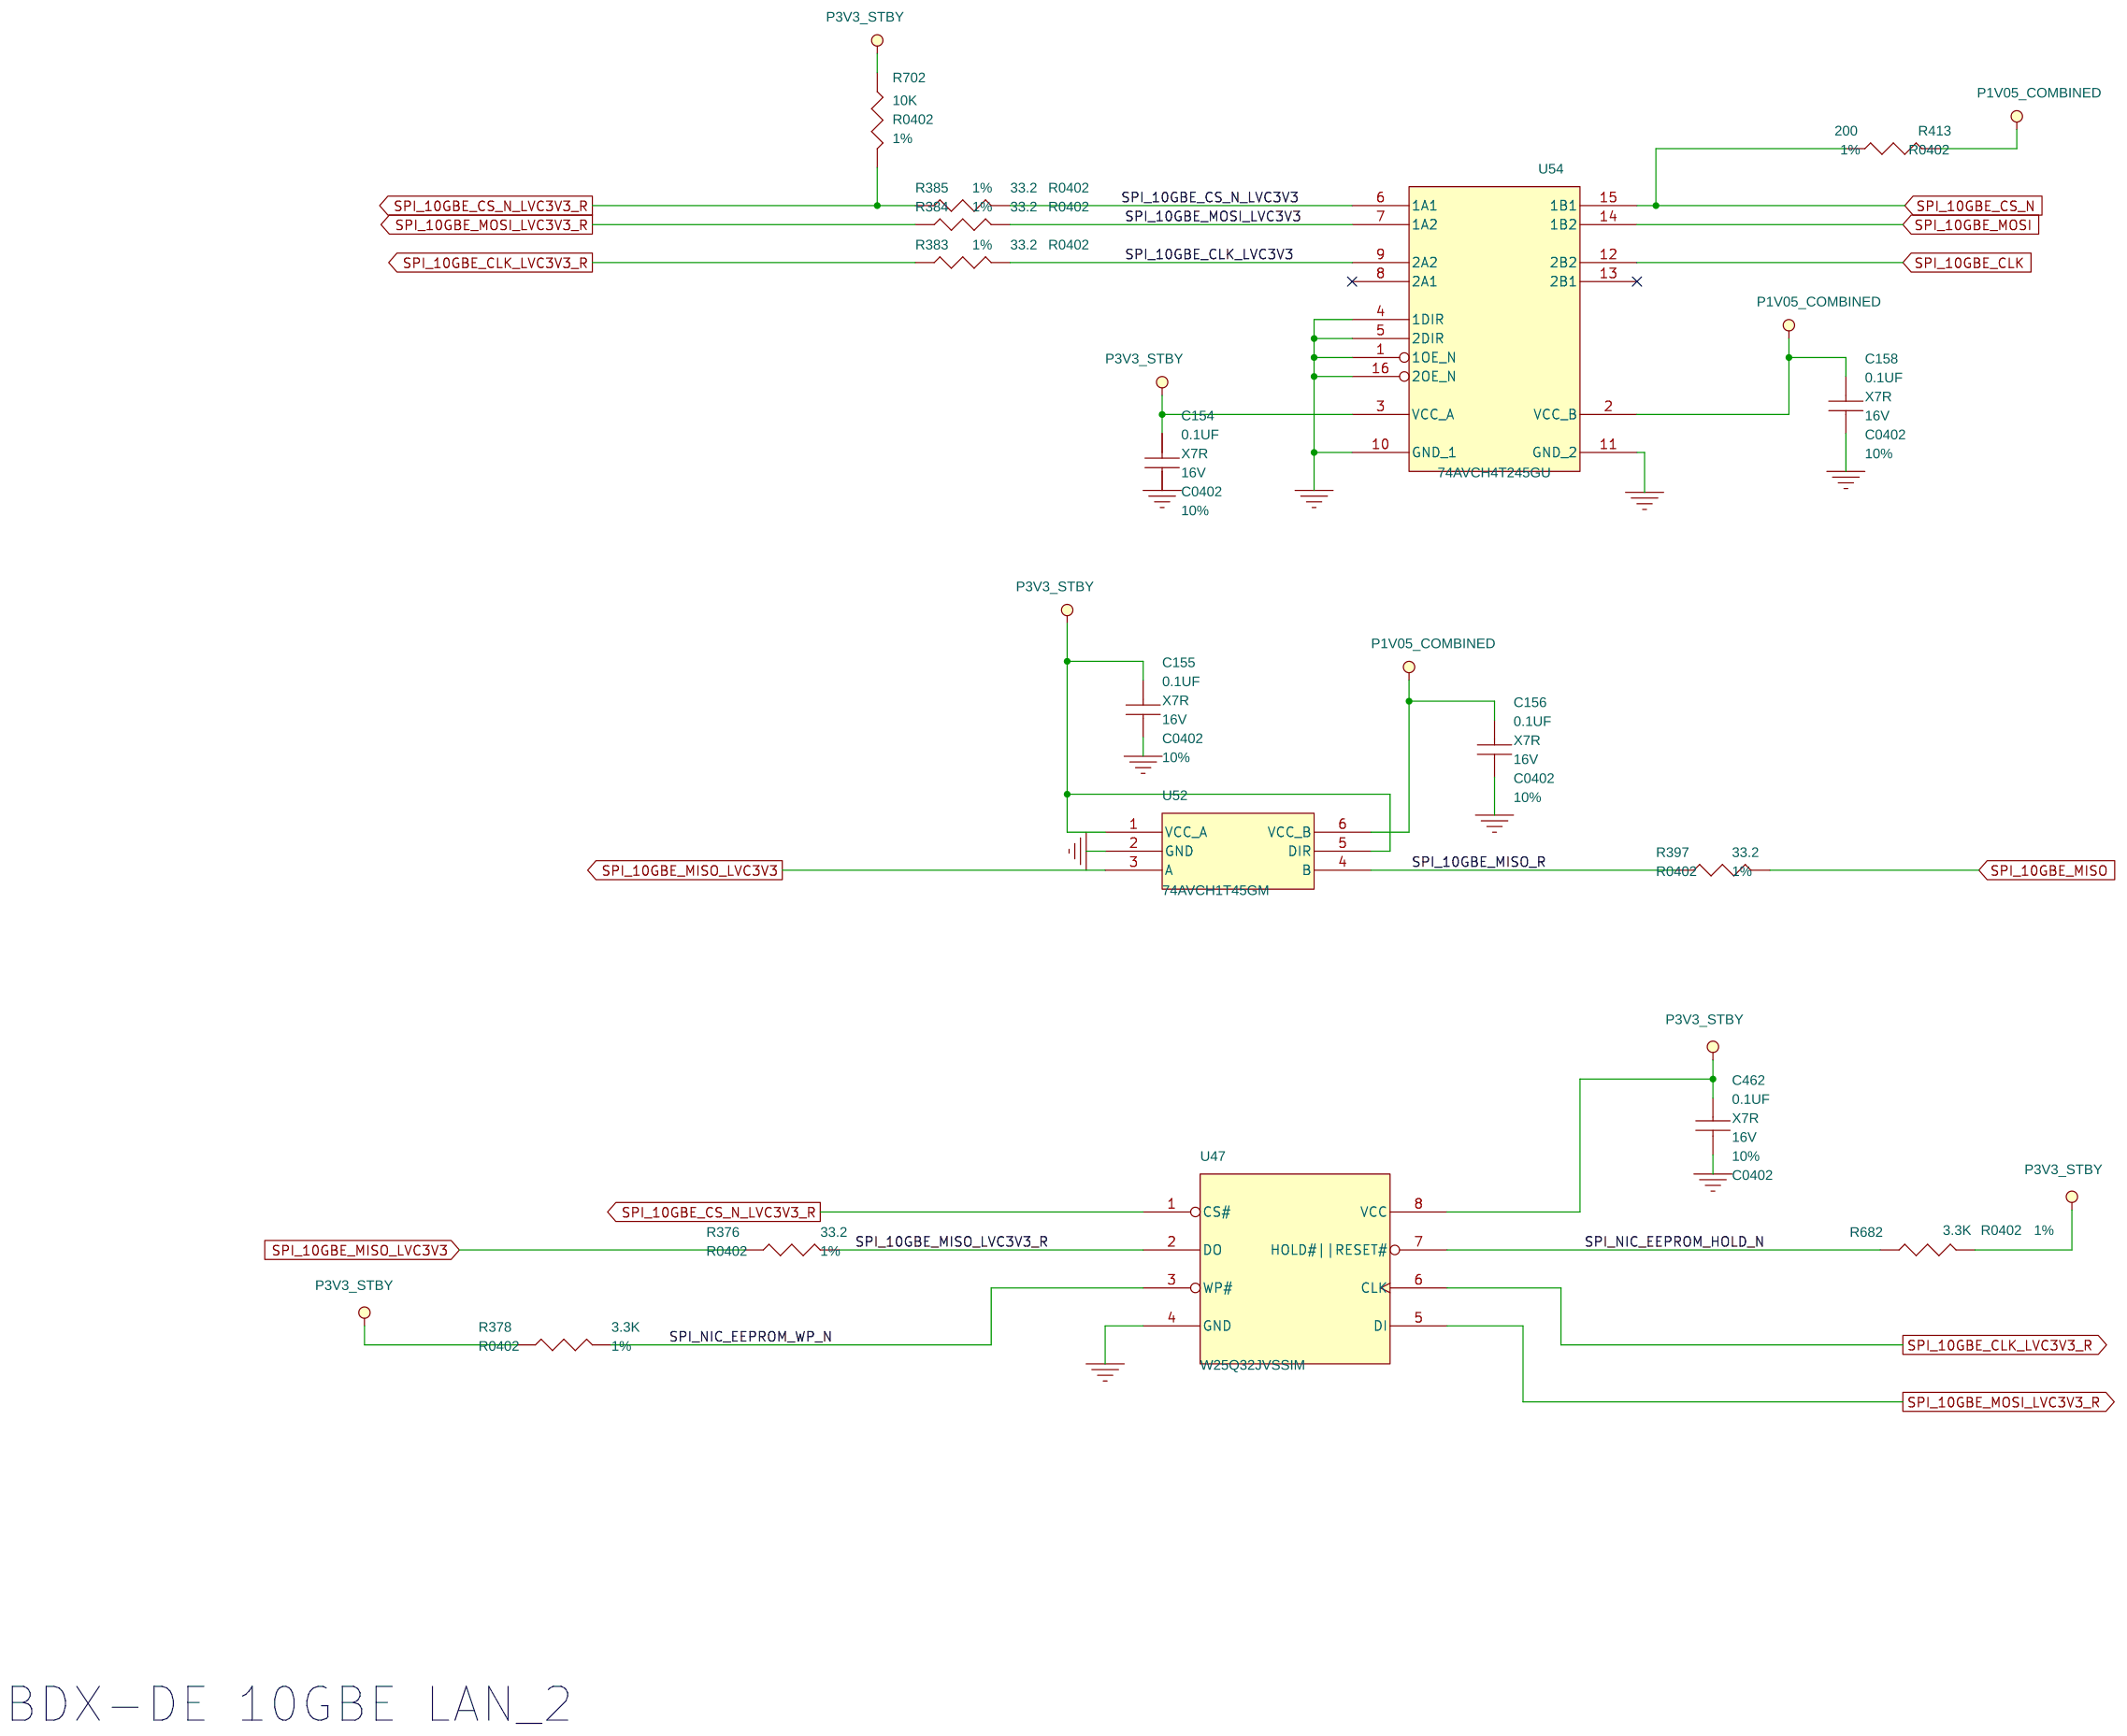
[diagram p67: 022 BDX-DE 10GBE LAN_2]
80 068 DELTA-L AND TDR_2: size B
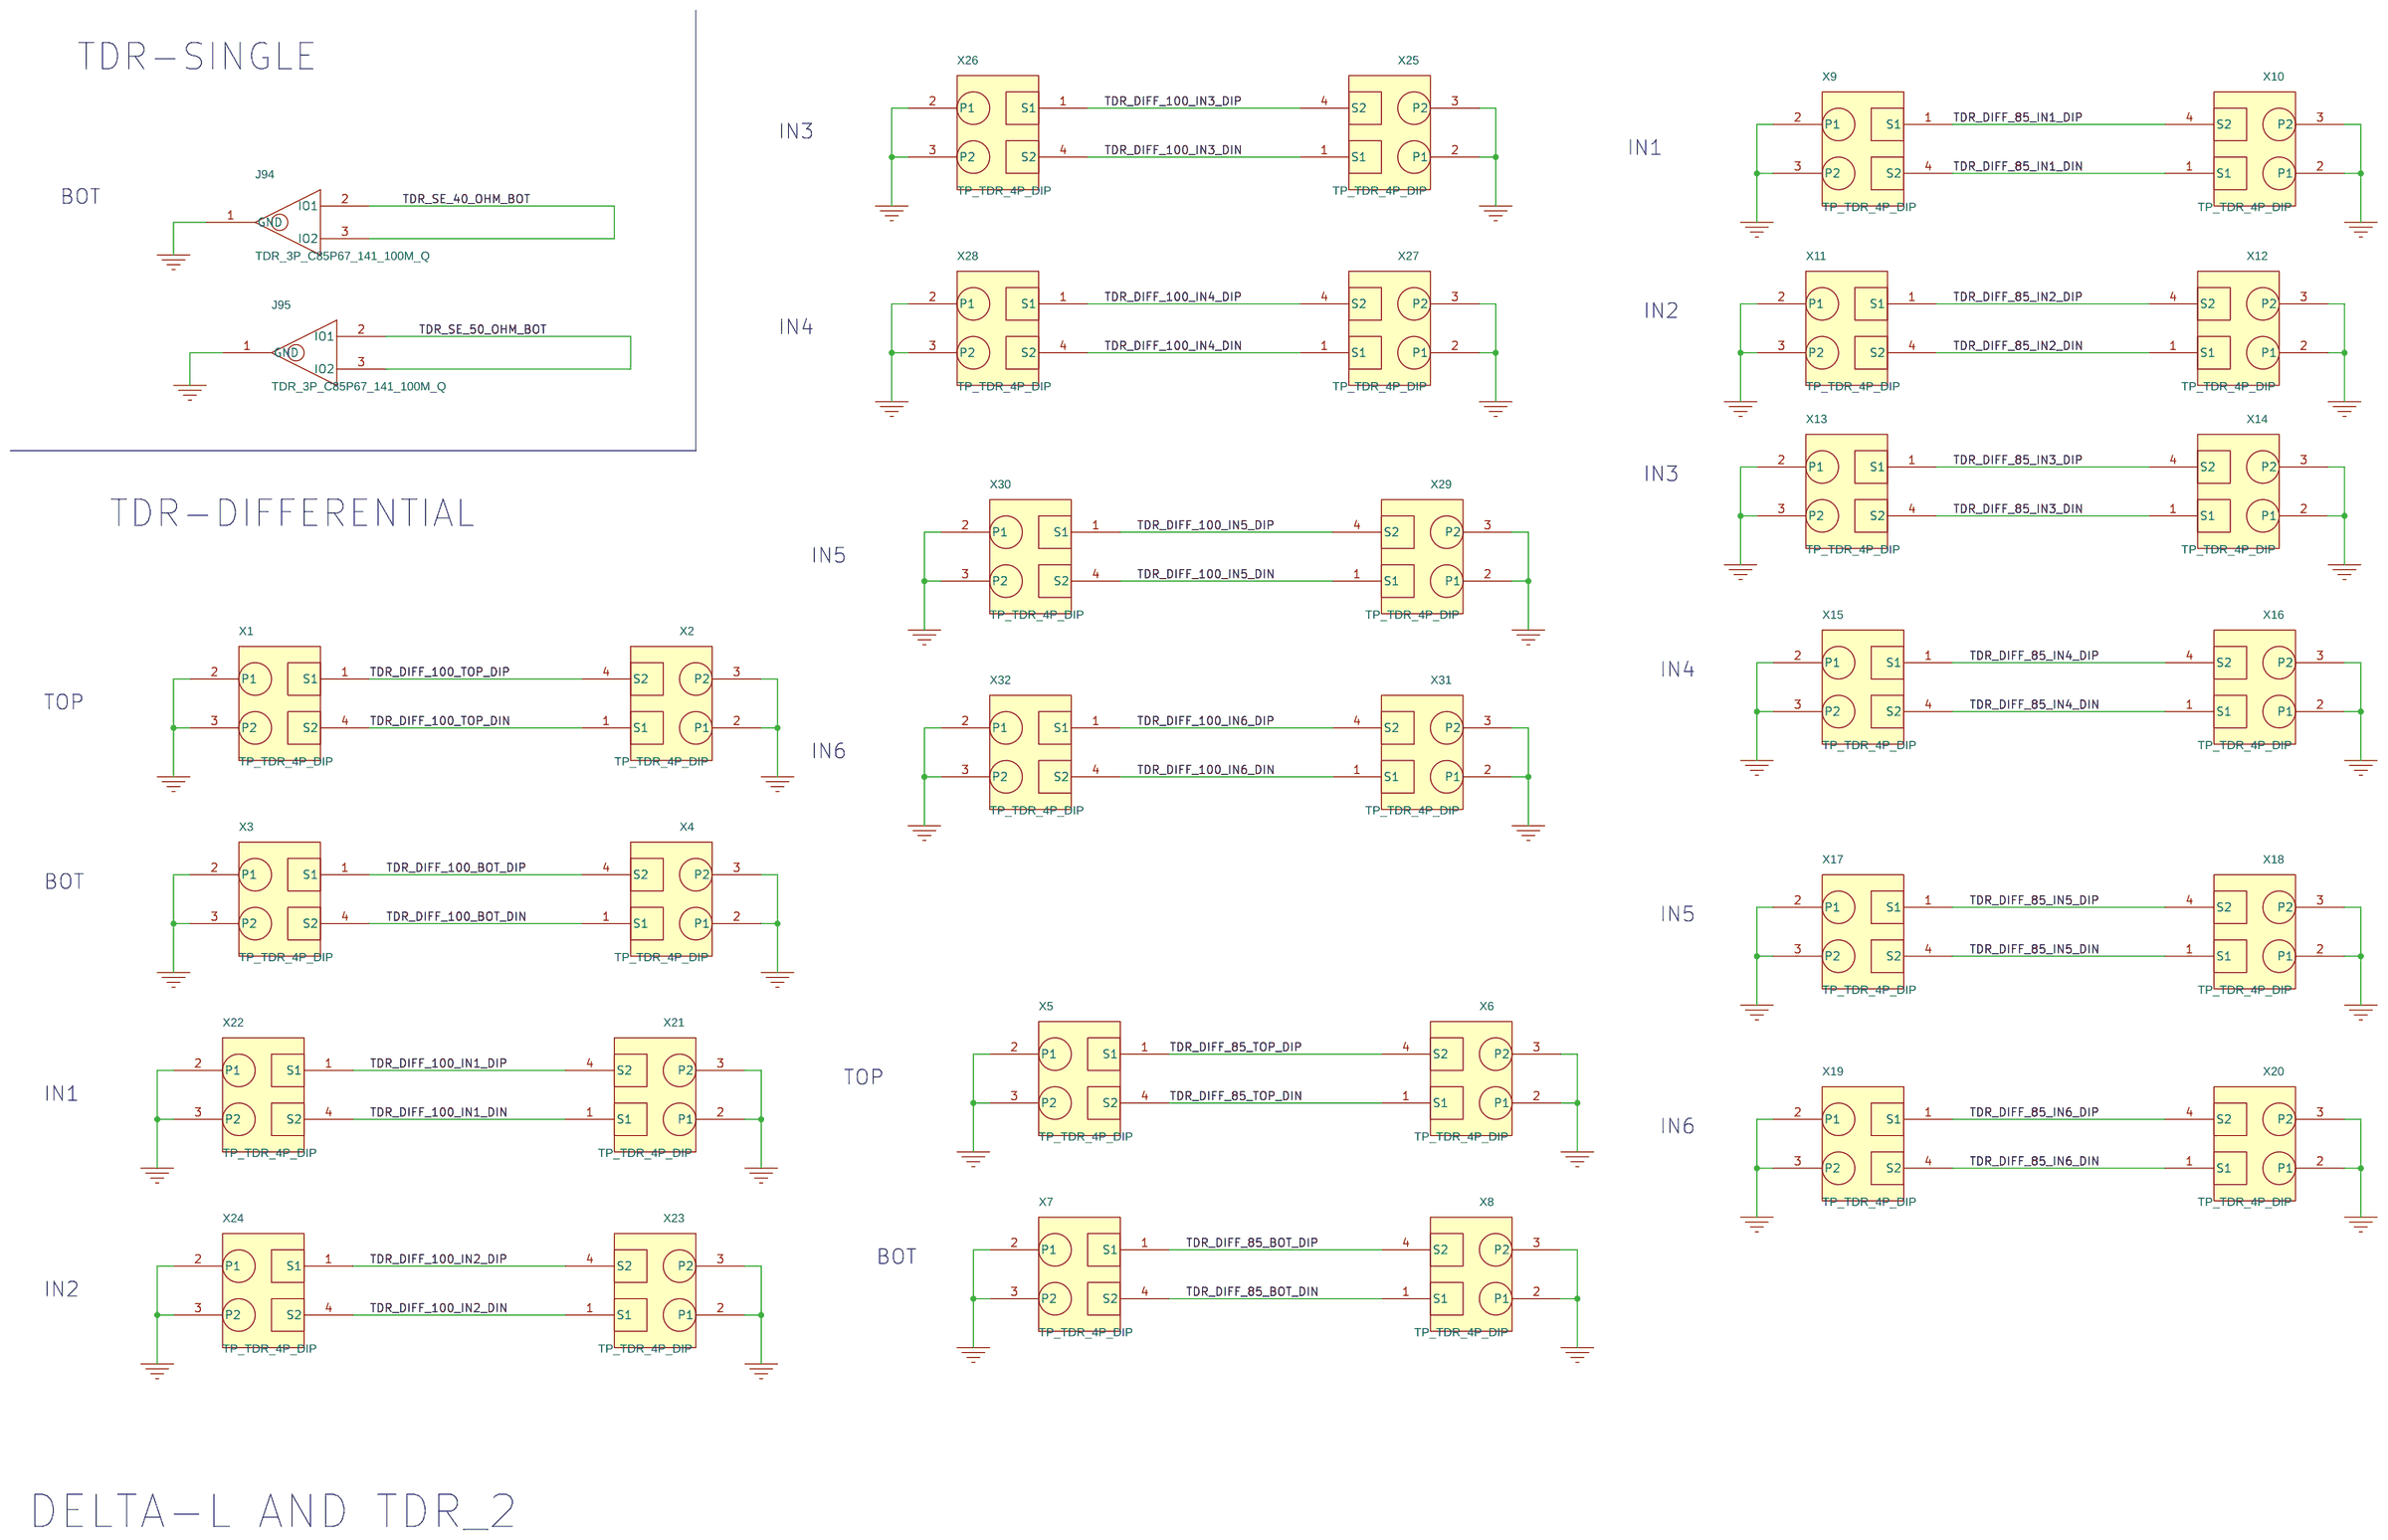
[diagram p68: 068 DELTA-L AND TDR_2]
81 070 RSMRST_SYSRST: size B
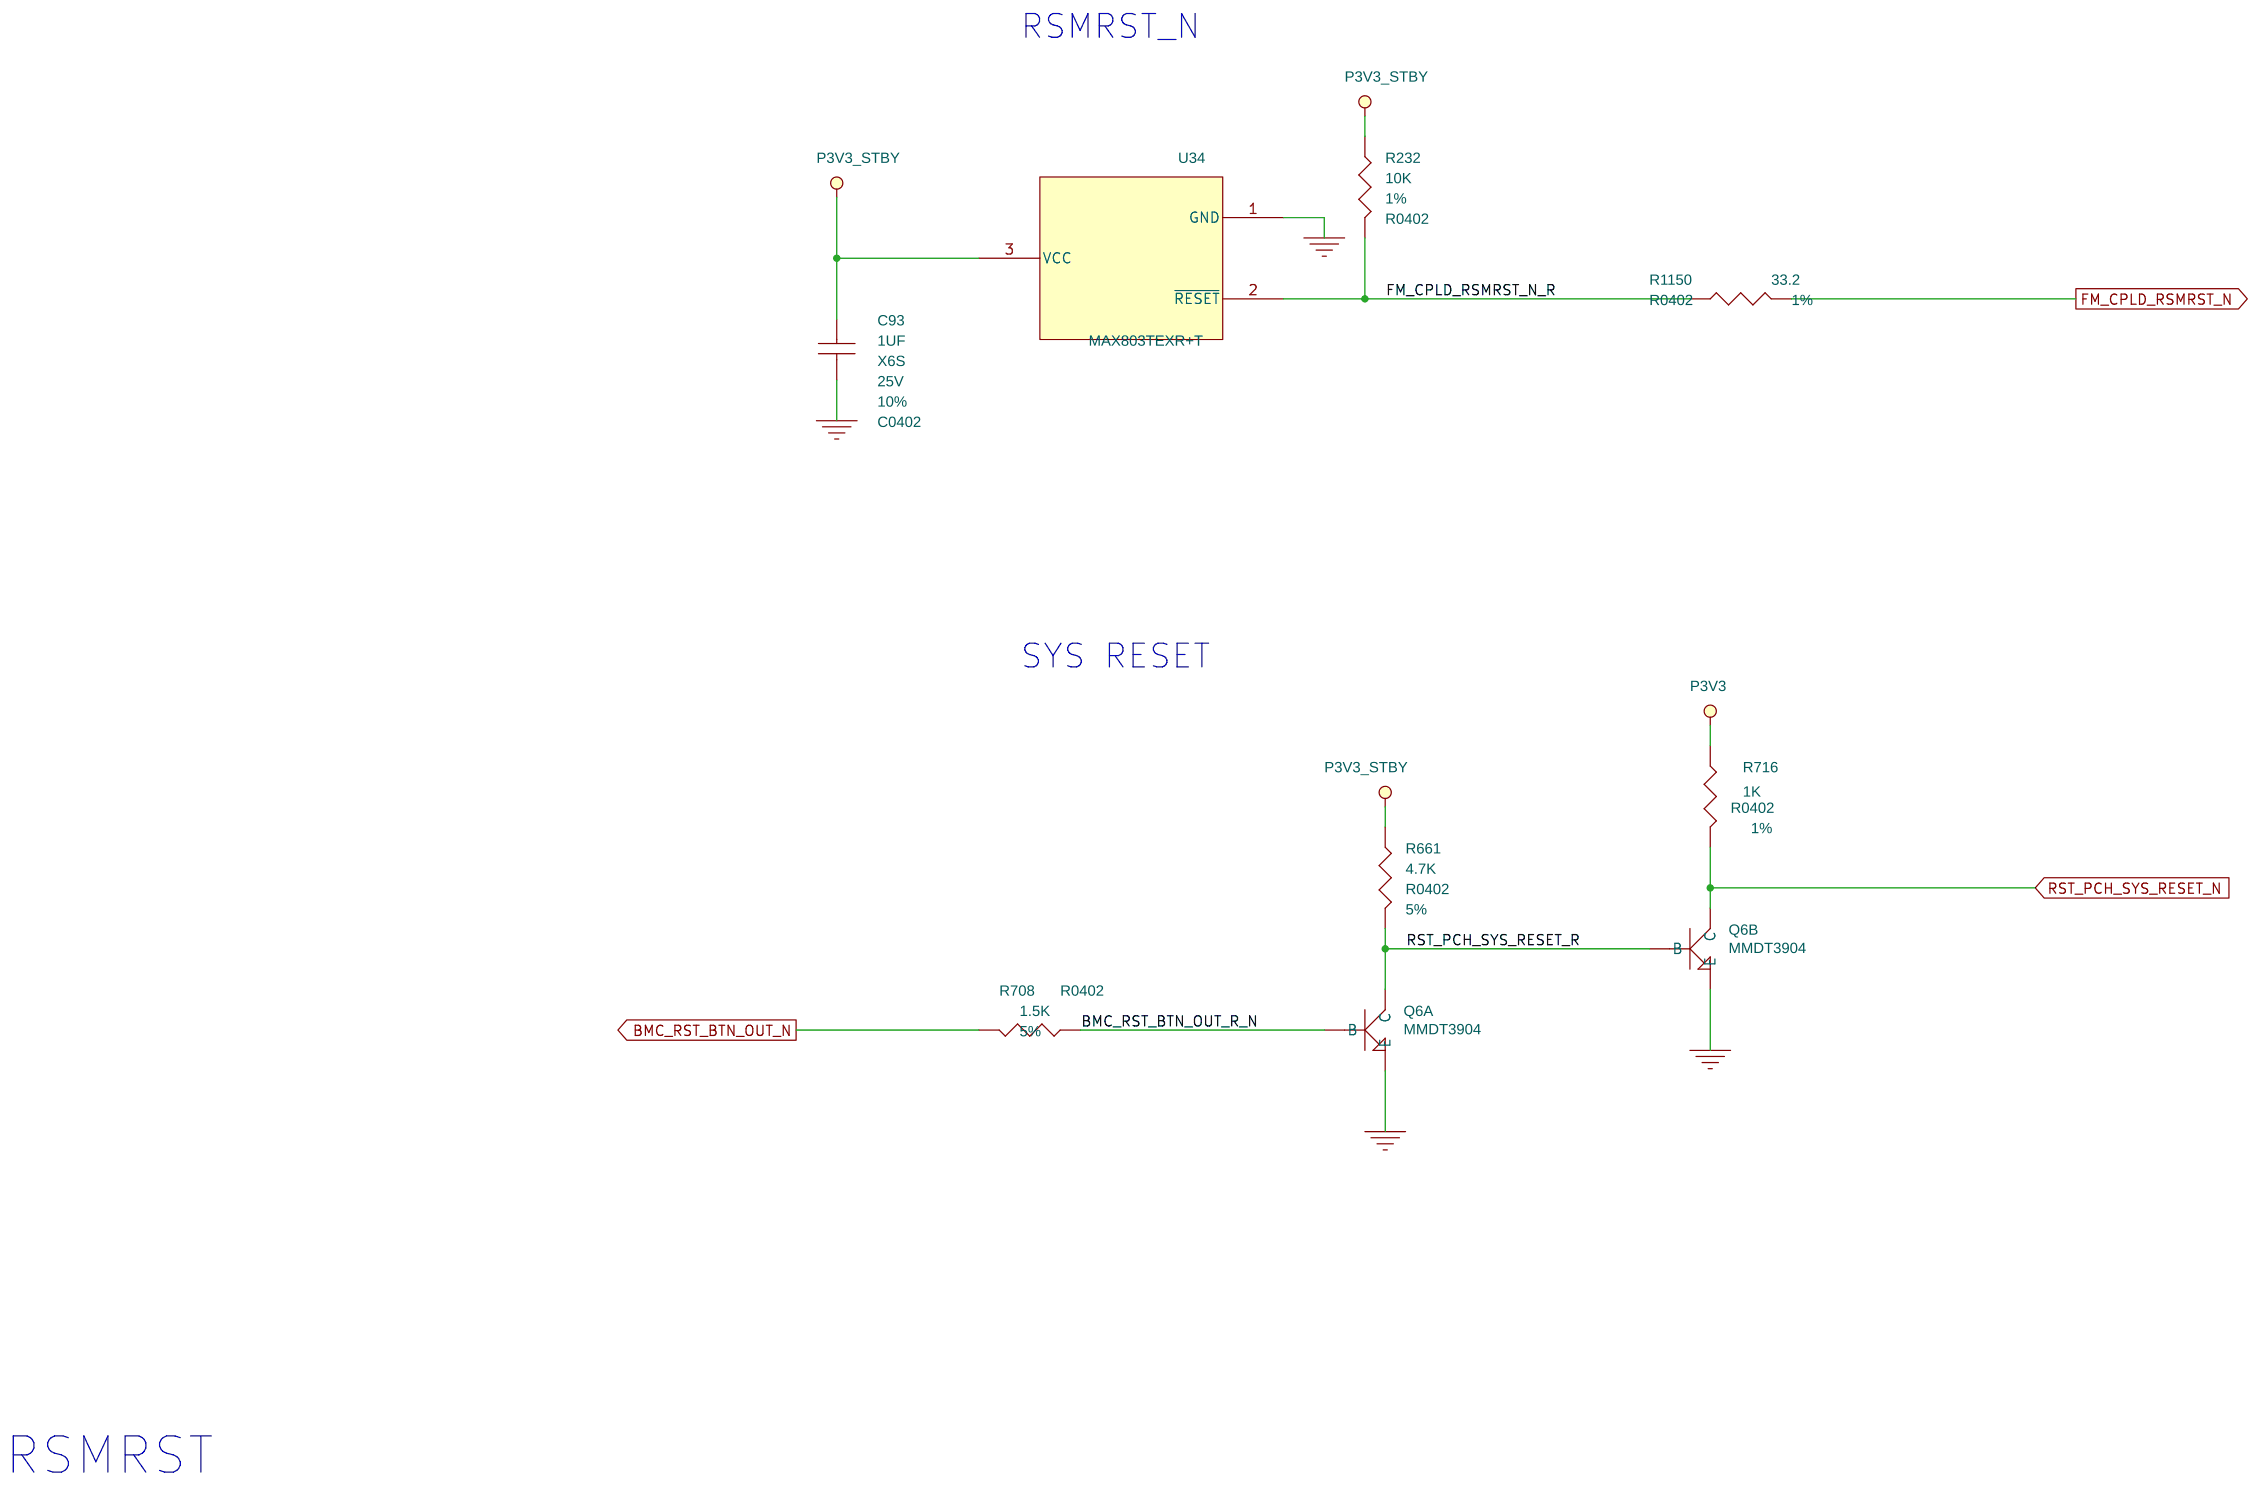
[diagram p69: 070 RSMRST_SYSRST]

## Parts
sheet 022 BDX-DE 10GBE LAN_2
C154  0.1UF  [C0402]
C155  0.1UF  [C0402]
C156  0.1UF  [C0402]
C158  0.1UF  [C0402]
C462  0.1UF  [C0402]
R376  33.2  [R0402]
R378  3.3K  [R0402]
R383  33.2  [R0402]
R384  33.2  [R0402]
R385  33.2  [R0402]
R397  33.2  [R0402]
R413  200  [R0402]
R682  3.3K  [R0402]
R702  10K  [R0402]
U47  W25Q32JVSSIM  [SOIC8_1-27_5-28X5-28XA]
U52  74AVCH1T45GM  [SOT886]
U54  74AVCH4T245GU  [XQFN16]
sheet 063 SNOWFLAKE_3
C256  2.2UF  [C0603]
C258  0.01UF  [C0402]
C259  1UF  [C0402]
C263  0.1UF  [C0402]
C264  0.1UF  [C0402]
C265  0.1UF  [C0402]
C266  1UF  [C0402]
C267  0.01UF  [C0402]
C268  0.1UF  [C0402]
C269  0.1UF  [C0402]
C271  0.1UF  [C0402]
C272  0.01UF  [C0402]
C273  0.1UF  [C0402]
C275  1UF  [C0402]
C278  0.1UF  [C0402]
C280  1UF  [C0402]
R95  1K  [R0402]
R99  1K  [R0402]
R109  22  [R0402]
R192  4.7K  [R0402]
R479  4.7K  [R0402]
R480  4.7K  [R0402]
R508  4.7K  [R0402]
R510  4.7K  [R0402]
R511  2.21K  [R0402]
R514  2.21K  [R0402]
R529  22  [R0402]
R632  4.7K  [R0402]
R1197  33.2  [R0402]
R1198  33.2  [R0402]
R1199  4.7K  [R0402]
R1200  4.7K  [R0402]
R1201  22  [R0402]
R1202  22  [R0402]
R1205  22  [R0402]
R1206  22  [R0402]
R1398  4.7K  [R0402]
R1434  33.2  [R0402]
R1435  33.2  [R0402]
R1436  33.2  [R0402]
R1437  33.2  [R0402]
U14  XM4E129BNCZADI2  [BGA212]  (sections A,B,C)
sheet 064 VOLTAGE MONITOR
C70  47PF  [C0402]
C72  47PF  [C0402]
C76  47PF  [C0402]
C289  47PF  [C0402]
C293  0.1UF  [C0402]
C294  0.1UF  [C0402]
C295  0.1UF  [C0402]
C308  0.1UF  [C0402]
R38  200K  [R0402]
R40  100K  [R0201]
R56  0  [R0603]
R65  100K  [R0402]
R70  0  [R0603]
R73  5.11K  [R0402]
R78  1.02K  [R0402]
R80  34.8K  [R0402]
R83  8.25K  [R0402]
R91  5.11K  [R0402]
R98  5.11K  [R0402]
R100  51.1K  [R0402]
R114  8.25K  [R0402]
R517  0  [R0603]
R1407  100K  [R0201]
R1408  0  [R0402]
U10  2N7002KW  [SOT323XB]
U123  PJC7428  [SOT323_GDS_2X1-25]
sheet 065 SMBUS ISOLATOR
C168  0.1UF  [C0402]
C200  0.1UF  [C0402]
C224  0.1UF  [C0402]
C229  0.1UF  [C0402]
C245  0.1UF  [C0402]
C248  0.1UF  [C0402]
R427  33.2  [R0402]
R441  1K  [R0402]
R442  33.2  [R0402]
R443  1K  [R0402]
R444  33.2  [R0402]
R446  1K  [R0402]
R449  10  [R0402]
R450  240  [R0402]
R451  240  [R0402]
R455  10  [R0402]
R457  2.21K  [R0402]
R459  2.21K  [R0402]
R462  33.2  [R0402]
R464  33.2  [R0402]
R1306  4.7K  [R0402]
R1307  4.7K  [R0402]
R1308  4.7K  [R0402]
R1309  4.7K  [R0402]
R1365  2.21K  [R0402]
U4  PCA9617ADP  [TSSOP8_3XB]
U58  PCA9617ADP  [TSSOP8_3XB]
U62  PCA9617ADP  [TSSOP8_3XB]
sheet 066 PWR_ PORT 80 LED
C608  0.1UF  [C0402]
D3  LED_YELL/GRE  [LED2S_27-21G6C-AN2Q1B3C]
D4  LED_YELL/GRE  [LED2S_27-21G6C-AN2Q1B3C]
D5  LED_YELL/GRE  [LED2S_27-21G6C-AN2Q1B3C]
D6  LED_YELL/GRE  [LED2S_27-21G6C-AN2Q1B3C]
D7  LED_YELL/GRE  [LED2S_27-21G6C-AN2Q1B3C]
D8  LED_YELL/GRE  [LED2S_27-21G6C-AN2Q1B3C]
D9  LED_YELL/GRE  [LED2S_27-21G6C-AN2Q1B3C]
D10  LED_YELL/GRE  [LED2S_27-21G6C-AN2Q1B3C]
D12  LED_BLUE  [LED2S_27-21BHC-ZM2N2TY3C]
D14  LED_YELL/GRE  [LED2S_27-21G6C-AN2Q1B3C]
D15  LED_YELL/GRE  [LED2S_27-21G6C-AN2Q1B3C]
D16  LED_YELL/GRE  [LED2S_27-21G6C-AN2Q1B3C]
D17  LED_YELL/GRE  [LED2S_27-21G6C-AN2Q1B3C]
Q7  2N7002KDW  [SOT363XD]
Q8  2N7002KDW  [SOT363XD]
R21  10K  [R0402]
R151  220  [R0402]
R154  220  [R0402]
R157  220  [R0402]
R164  220  [R0402]
R169  220  [R0402]
R461  470  [R0402]
R558  220  [R0402]
R566  220  [R0402]
R569  220  [R0402]
R802  220  [R0402]
R803  220  [R0402]
R804  220  [R0402]
R805  220  [R0402]
U6  SN74LVC1G07DCKR  [SC70-5XB]
sheet 067 DELTA-L AND TDR_1
J44  DELTA-L  [TRIANG_LAUNCH_3PXA]
J45  DELTA-L  [TRIANG_LAUNCH_3PXA]
J46  DELTA-L  [TRIANG_LAUNCH_3PXA]
J47  DELTA-L  [TRIANG_LAUNCH_3PXA]
J48  DELTA-L  [TRIANG_LAUNCH_3PXA]
J49  DELTA-L  [TRIANG_LAUNCH_3PXA]
J50  DELTA-L  [TRIANG_LAUNCH_3PXA]
J51  DELTA-L  [TRIANG_LAUNCH_3PXA]
J52  DELTA-L  [TRIANG_LAUNCH_3PXA]
J53  DELTA-L  [TRIANG_LAUNCH_3PXA]
J54  DELTA-L  [TRIANG_LAUNCH_3PXA]
J55  DELTA-L  [TRIANG_LAUNCH_3PXA]
J56  DELTA-L  [TRIANG_LAUNCH_3PXA]
J57  DELTA-L  [TRIANG_LAUNCH_3PXA]
J58  DELTA-L  [TRIANG_LAUNCH_3PXA]
J59  DELTA-L  [TRIANG_LAUNCH_3PXA]
J60  DELTA-L  [TRIANG_LAUNCH_3PXA]
J61  DELTA-L  [TRIANG_LAUNCH_3PXA]
J62  DELTA-L  [TRIANG_LAUNCH_3PXA]
J63  DELTA-L  [TRIANG_LAUNCH_3PXA]
J64  DELTA-L  [TRIANG_LAUNCH_3PXA]
J65  DELTA-L  [TRIANG_LAUNCH_3PXA]
J66  DELTA-L  [TRIANG_LAUNCH_3PXA]
J67  DELTA-L  [TRIANG_LAUNCH_3PXA]
J68  DELTA-L  [TRIANG_LAUNCH_3PXA]
J69  DELTA-L  [TRIANG_LAUNCH_3PXA]
J70  DELTA-L  [TRIANG_LAUNCH_3PXA]
J71  DELTA-L  [TRIANG_LAUNCH_3PXA]
J76  DELTA-L  [TRIANG_LAUNCH_3PXA]
J77  DELTA-L  [TRIANG_LAUNCH_3PXA]
J78  DELTA-L  [TRIANG_LAUNCH_3PXA]
J79  DELTA-L  [TRIANG_LAUNCH_3PXA]
J80  TDR_3P_C85P67_141_100M_Q  [TDR_3P_C85P67_141_100M_Q]
J81  TDR_3P_C85P67_141_100M_Q  [TDR_3P_C85P67_141_100M_Q]
J82  TDR_3P_C85P67_141_100M_Q  [TDR_3P_C85P67_141_100M_Q]
J83  TDR_3P_C85P67_141_100M_Q  [TDR_3P_C85P67_141_100M_Q]
J84  TDR_3P_C85P67_141_100M_Q  [TDR_3P_C85P67_141_100M_Q]
J85  TDR_3P_C85P67_141_100M_Q  [TDR_3P_C85P67_141_100M_Q]
J86  TDR_3P_C85P67_141_100M_Q  [TDR_3P_C85P67_141_100M_Q]
J87  TDR_3P_C85P67_141_100M_Q  [TDR_3P_C85P67_141_100M_Q]
J88  TDR_3P_C85P67_141_100M_Q  [TDR_3P_C85P67_141_100M_Q]
J89  TDR_3P_C85P67_141_100M_Q  [TDR_3P_C85P67_141_100M_Q]
J90  TDR_3P_C85P67_141_100M_Q  [TDR_3P_C85P67_141_100M_Q]
J91  TDR_3P_C85P67_141_100M_Q  [TDR_3P_C85P67_141_100M_Q]
J92  TDR_3P_C85P67_141_100M_Q  [TDR_3P_C85P67_141_100M_Q]
J93  TDR_3P_C85P67_141_100M_Q  [TDR_3P_C85P67_141_100M_Q]
sheet 068 DELTA-L AND TDR_2
J94  TDR_3P_C85P67_141_100M_Q  [TDR_3P_C85P67_141_100M_Q]
J95  TDR_3P_C85P67_141_100M_Q  [TDR_3P_C85P67_141_100M_Q]
X1  TP_TDR_4P_DIP  [MPKT4_H025P0200]
X2  TP_TDR_4P_DIP  [MPKT4_H025P0200]
X3  TP_TDR_4P_DIP  [MPKT4_H025P0200]
X4  TP_TDR_4P_DIP  [MPKT4_H025P0200]
X5  TP_TDR_4P_DIP  [MPKT4_H025P0200]
X6  TP_TDR_4P_DIP  [MPKT4_H025P0200]
X7  TP_TDR_4P_DIP  [MPKT4_H025P0200]
X8  TP_TDR_4P_DIP  [MPKT4_H025P0200]
X9  TP_TDR_4P_DIP  [MPKT4_H025P0200]
X10  TP_TDR_4P_DIP  [MPKT4_H025P0200]
X11  TP_TDR_4P_DIP  [MPKT4_H025P0200]
X12  TP_TDR_4P_DIP  [MPKT4_H025P0200]
X13  TP_TDR_4P_DIP  [MPKT4_H025P0200]
X14  TP_TDR_4P_DIP  [MPKT4_H025P0200]
X15  TP_TDR_4P_DIP  [MPKT4_H025P0200]
X16  TP_TDR_4P_DIP  [MPKT4_H025P0200]
X17  TP_TDR_4P_DIP  [MPKT4_H025P0200]
X18  TP_TDR_4P_DIP  [MPKT4_H025P0200]
X19  TP_TDR_4P_DIP  [MPKT4_H025P0200]
X20  TP_TDR_4P_DIP  [MPKT4_H025P0200]
X21  TP_TDR_4P_DIP  [MPKT4_H025P0200]
X22  TP_TDR_4P_DIP  [MPKT4_H025P0200]
X23  TP_TDR_4P_DIP  [MPKT4_H025P0200]
X24  TP_TDR_4P_DIP  [MPKT4_H025P0200]
X25  TP_TDR_4P_DIP  [MPKT4_H025P0200]
X26  TP_TDR_4P_DIP  [MPKT4_H025P0200]
X27  TP_TDR_4P_DIP  [MPKT4_H025P0200]
X28  TP_TDR_4P_DIP  [MPKT4_H025P0200]
X29  TP_TDR_4P_DIP  [MPKT4_H025P0200]
X30  TP_TDR_4P_DIP  [MPKT4_H025P0200]
X31  TP_TDR_4P_DIP  [MPKT4_H025P0200]
X32  TP_TDR_4P_DIP  [MPKT4_H025P0200]
sheet 069 DELTA-L AND TDR_3
J96  DELTA-L  [TRIANG_LAUNCH_3PXA]
J97  DELTA-L  [TRIANG_LAUNCH_3PXA]
J98  DELTA-L  [TRIANG_LAUNCH_3PXA]
J99  DELTA-L  [TRIANG_LAUNCH_3PXA]
J100  DELTA-L  [TRIANG_LAUNCH_3PXA]
J101  DELTA-L  [TRIANG_LAUNCH_3PXA]
J102  DELTA-L  [TRIANG_LAUNCH_3PXA]
J103  DELTA-L  [TRIANG_LAUNCH_3PXA]
J104  TDR_3P_C85P67_141_100M_Q  [TDR_3P_C85P67_141_100M_Q]
J105  TDR_3P_C85P67_141_100M_Q  [TDR_3P_C85P67_141_100M_Q]
J106  TDR_3P_C85P67_141_100M_Q  [TDR_3P_C85P67_141_100M_Q]
J107  TDR_3P_C85P67_141_100M_Q  [TDR_3P_C85P67_141_100M_Q]
X33  TP_TDR_4P_DIP  [MPKT4_H025P0200]
X34  TP_TDR_4P_DIP  [MPKT4_H025P0200]
X35  TP_TDR_4P_DIP  [MPKT4_H025P0200]
X36  TP_TDR_4P_DIP  [MPKT4_H025P0200]
X37  TP_TDR_4P_DIP  [MPKT4_H025P0200]
X38  TP_TDR_4P_DIP  [MPKT4_H025P0200]
X39  TP_TDR_4P_DIP  [MPKT4_H025P0200]
X40  TP_TDR_4P_DIP  [MPKT4_H025P0200]
sheet 070 RSMRST_SYSRST
C93  1UF  [C0402]
Q6  MMDT3904  [SOT363A]  (sections A,B)
R232  10K  [R0402]
R661  4.7K  [R0402]
R708  1.5K  [R0402]
R716  1K  [R0402]
R1150  33.2  [R0402]
U34  MAX803TEXR+T  [SC70_123_2X1-25XA]

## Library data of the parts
C154-C156 C158 C168 C200 C224 C229 C245 C248 = CAP_NP: CAP CHIP 0.1U 16V(10%.X7R.0402); CLASS: DISCRETE; CMPLS_LVL: EP(V1); Data: MUR_LF_CAP SERIES_1.pdf; From_pj: S5A-TRAVIS; Lifecycle: Comp-Approve; MATERIAL: X7R; Manuf_PN: WBM155R71C104K; Manuf_name: MURATA ERIE N.A. INC TAIWAN BRANCH Okayama Murata Mfg.Co..Ltd. Wakura Murata Mfg; Manufacturer: MUR; Manuftr: MUR; Part_Type: *LF_C0402; RD_CMPLS_LVL: EP(V1); ROOM: VR_P1V05_PCH; TOLERANCE: 10%; Top_bot: TOP; VOLTAGE: 16V; fp_ECN: 0402 SERIES_LL34.xls
C462 = CAP_NP: CAP CHIP 0.1U 16V(10%.X7R.0402); CLASS: DISCRETE; CMPLS_LVL: EP(V1); Data: MUR_LF_CAP SERIES_1.pdf; From_pj: S5A-TRAVIS; Lifecycle: Comp-Approve; MATERIAL: X7R; Manuf_PN: WBM155R71C104K; Manuf_name: MURATA ERIE N.A. INC TAIWAN BRANCH Okayama Murata Mfg.Co..Ltd. Wakura Murata Mfg; Manufacturer: MUR; Manuftr: MUR; Part_Type: *LF_C0402; RD_CMPLS_LVL: EP(V1); TOLERANCE: 10%; VOLTAGE: 16V; fp_ECN: 0402 SERIES_LL34.xls; top_bot: BOT
R376 R383-R385 R397 = R: RES CHIP 33.2 1/16W +-1%(0402); CLASS: DISCRETE; CMPLS_LVL: EP; Data: CYN_LF_RL SERIES.pdf; From_pj: A06-EDISON; Lifecycle: Comp-Approve; MATERIAL: CHIP; Manuf_PN: RR0510S-33R2-FN; Manuf_name: CYNTEC CO.. LTD.; Manufacturer: CYN; Manuftr: CYN; Part_Type: *LF_Resistor; TOLERANCE: 1%; WATTAGE: 1/16W; fp_ECN: 0402 SERIES_LL34.xls; top_bot: TOP
R378 R682 = R: RES CHIP 3.3K 1/16W +-1%(0402); CLASS: DISCRETE; CMPLS_LVL: EP; Data: TAI_LF_RM SERIES-2.pdf; From_pj: S75-LA; Lifecycle: Comp-Approve; MATERIAL: CHIP; Manuf_PN: RM04FTN3301; Manuf_name: TA-I TECHNOLOGY CO..LTD.; Manuftr: TAI; Part_Type: *LF_Resistor; Standard: ##; Status: Preferred; TOLERANCE: 1%; WATTAGE: 1/16W; fp_ECN: 0402 SERIES_LL34.xls
R413 = R: RES CHIP 200 1/16W +-1%(0402); CLASS: DISCRETE; CMPLS_LVL: EP; Data: WTC_LF_WR SERIES-4.pdf; From_pj: S79-C.Y.HUANG; Lifecycle: Comp-Approve; MATERIAL: CHIP; Manuf_PN: WR04X2000FTL; Manuf_name: WALSIN TECHNOLOGY CORPORATION; Manuftr: WTC; Part_Type: *LF_Resistor; TOLERANCE: 1%; WATTAGE: 1/16W; fp_ECN: 0402 SERIES_LL34.xls
R21 R232 R702 = R: RES CHIP 10K 1/16W +-1% (0402); CLASS: DISCRETE; CMPLS_LVL: EP; Data: WTC_LF_WR SERIES.pdf; From_pj: S82; Lifecycle: Comp-Approve; MATERIAL: CHIP; Manuf_PN: RR0510S-103-FN; Manuf_name: CYNTEC CO.. LTD.; Manuftr: CYN; Part_Type: *LF_Resistor; Status: Preferred; TOLERANCE: 1%; WATTAGE: 1/16W; fp_ECN: 0402 SERIES_LL34.xls
U47 = W25Q32JVSSIM: IC FLASH(8P)W25Q32JVSSIM(SOIC); CLASS: IC; Data: WND_W25Q32JVSSIM.pdf; From_pj: T2MK-MARK; Lifecycle: Comp-Release Qty; MATERIAL: IC; Manuf_name: WINBOND ELECTRONICS CORP.; Manuftr: WND; Part_Type: *LF_Chipset; RD_CMPLS_LVL: EP(V1)
U52 = 74AVCH1T45GM: IC OTHER(6P) 74AVCH1T45GM(XSON); CLASS: IC; CMPLS_LVL: EP(V1); Data: NXP_74AVCH1T45GM_REV4.pdf; From_pj: F07-HENRY; Lifecycle: Comp-Approve; MATERIAL: IC; Manuf_name: NXP semiconductors; Manuftr: NXP; Part_Type: *LF_Chipset; RD_CMPLS_LVL: EP(V1); Standard: Potential
U54 = 74AVCH4T245GU: IC OTHER(16P) 74AVCH4T245GU(XQFN); CLASS: IC; CMPLS_LVL: EP(V1); Data: NXP_74AVCH4T245GU_REV4.pdf; From_pj: F07-HENRY; Lifecycle: Comp-Approve; MATERIAL: IC; Manuf_name: NXP semiconductors; Manuftr: NXP; Part_Type: *LF_Chipset; RD_CMPLS_LVL: EP(V1); Standard: Potential
C256 = CAP_NP: CAP CHIP 2.2UF 6.3V(+-10%.X7R.0603); CLASS: DISCRETE; CMPLS_LVL: EP; Data: SAM_MLCC.pdf; From_pj: S99Q-JACK; Lifecycle: Comp-Approve; MATERIAL: X7R; Manuf_PN: CL10B225KQ8NNNC; Manuf_name: SAMSUNG ELECTRONICS CO..LTD SAMSUNG SDI CO..LTD; Manuftr: SAM; Part_Type: *LF_C0603; Standard: End of Design; TOLERANCE: 10%; VOLTAGE: 6.3V
C258 C267 C272 = CAP_NP: CAP CHIP 0.01U 50V(+-10%,X7R,0402); CLASS: DISCRETE; CMPLS_LVL: EP(V1); Data: MUR_MLCC_20110826.pdf; From_pj: T2B-CHEESE; Lifecycle: Comp-Approve; MATERIAL: X7R; Manuf_PN: WBM155R71H103K; Manuf_name: MURATA ERIE N.A. INC TAIWAN BRANCH Okayama Murata Mfg.Co.,Ltd.; Manuftr: MUR; Part_Type: *LF_C0402; RD_CMPLS_LVL: EP(V1); TOLERANCE: 10%; VOLTAGE: 50V; fp_ECN: 0402 SERIES_LL34.xls
C259 C266 C275 C280 = CAP_NP: CAP CHIP 1U.6.3V(+-10%.X7R.0402); CLASS: DISCRETE; CMPLS_LVL: EP(V1); Data: MKP_LF_CAP SERIES.pdf; From_pj: T94-JEFF; Lifecycle: Comp-Approve; MATERIAL: X7R; Manuf_PN: MAG02X7R0J105K; Manuf_name: Matsuki Precision Ceramic Co.. Ltd.Matsuki Polymer Technology Co.. Ltd.; Manuftr: MKP; Part_Type: *LF_C0402; RD_CMPLS_LVL: EP(V1); TOLERANCE: 10%; VOLTAGE: 6.3V; fp_ECN: 0402 SERIES_LL34.xls
C263-C265 C268 C269 C271 C273 C278 C294 C295 C308 = CAP_NP: CAP CHIP 0.1U 16V(10%.X7R.0402); CLASS: DISCRETE; CMPLS_LVL: EP(V1); Data: MUR_LF_CAP SERIES_1.pdf; From_pj: S5A-TRAVIS; Lifecycle: Comp-Approve; MATERIAL: X7R; Manuf_PN: WBM155R71C104K; Manuf_name: MURATA ERIE N.A. INC TAIWAN BRANCH Okayama Murata Mfg.Co..Ltd. Wakura Murata Mfg; Manuftr: MUR; Part_Type: *LF_C0402; RD_CMPLS_LVL: EP(V1); TOLERANCE: 10%; VOLTAGE: 16V; fp_ECN: 0402 SERIES_LL34.xls
R95 R99 R441 R443 = R: RES CHIP 1K 1/16W +-1% (0402); CLASS: DISCRETE; CMPLS_LVL: EP; Data: WTC_LF_WR SERIES.pdf; Lifecycle: Comp-Approve; MATERIAL: CHIP; Manuf_PN: RR0510S-102-FN; Manuf_name: CYNTEC CO.. LTD.; Manuftr: CYN; Part_Type: *LF_Resistor; Status: Preferred; TOLERANCE: 1%; WATTAGE: 1/16W; fp_ECN: 0402 SERIES_LL34.xls
R109 R529 R1201 R1202 R1205 R1206 = R: RES CHIP 22 1/16W +-1%(0402); BOM: AST2300; CLASS: DISCRETE; CMPLS_LVL: EP; Data: RHT_LF_RES SERIES-2.pdf; From_pj: S75-L.A.; Lifecycle: Comp-Approve; MATERIAL: CHIP; Manuf_PN: CR0222R0F002S; Manuf_name: RTECH TECHNOLOGY CO..LTD. (Compostar); Manufacturer: CYN; Manuftr: RHT; Part_Type: *LF_Resistor; Standard: ##; Status: Preferred; TOLERANCE: 1%; WATTAGE: 1/16W; fp_ECN: 0402 SERIES_LL34.xls; top_bot: TOP
R192 R632 = R: RES CHIP 4.7K 1/16W +-5% (0402); BOM: AST2300; CLASS: DISCRETE; CMPLS_LVL: EP; Data: WTC_LF_WR SERIES.pdf; Lifecycle: Comp-Approve; MATERIAL: CHIP; Manuf_PN: RR0510S-472-JN; Manuf_name: CYNTEC CO.. LTD.; Manuftr: CYN; Part_Type: *LF_Resistor; Status: Preferred; TOLERANCE: 5%; WATTAGE: 1/16W; fp_ECN: 0402 SERIES_LL34.xls
R479 R480 R508 R510 R1306 R1308 R1398 = R: RES CHIP 4.7K 1/16W +-5% (0402); CLASS: DISCRETE; CMPLS_LVL: EP; Data: WTC_LF_WR SERIES.pdf; Lifecycle: Comp-Approve; MATERIAL: CHIP; Manuf_PN: RR0510S-472-JN; Manuf_name: CYNTEC CO.. LTD.; Manuftr: CYN; Part_Type: *LF_Resistor; Status: Preferred; TOLERANCE: 5%; WATTAGE: 1/16W; fp_ECN: 0402 SERIES_LL34.xls
R511 R514 = R: RES CHIP 2.21K 1/16W +-1% (0402); CLASS: DISCRETE; CMPLS_LVL: EP; Data: YGO_RC0201.pdf; From_pj: S36-TOD; Lifecycle: Comp-Approve; MATERIAL: CHIP; Manuf_PN: RC0402FR-072K21; Manuf_name: YAGEO CORPORATION; Manuftr: YGO; Part_Type: *LF_Resistor; TOLERANCE: 1%; WATTAGE: 1/16W; fp_ECN: 0402 SERIES_LL34.xls
R1197 R1198 R1434-R1437 = R: RES CHIP 33.2 1/16W +-1%(0402); BOM: AST2300; CLASS: DISCRETE; CMPLS_LVL: EP; Data: CYN_LF_RL SERIES.pdf; From_pj: A06-EDISON; Lifecycle: Comp-Approve; MATERIAL: CHIP; Manuf_PN: RR0510S-33R2-FN; Manuf_name: CYNTEC CO.. LTD.; Manufacturer: CYN; Manuftr: CYN; Part_Type: *LF_Resistor; TOLERANCE: 1%; WATTAGE: 1/16W; fp_ECN: 0402 SERIES_LL34.xls; top_bot: TOP
R1199 R1200 R1307 R1309 = R: RES CHIP 4.7K 1/16W +-5% (0402); CLASS: DISCRETE; CMPLS_LVL: EP; Data: WTC_LF_WR SERIES.pdf; Lifecycle: Comp-Approve; MATERIAL: CHIP; Manuf_PN: RR0510S-472-JN; Manuf_name: CYNTEC CO.. LTD.; Manuftr: CYN; Not_insert: NI; Part_Type: *LF_Resistor; Status: Preferred; TOLERANCE: 5%; WATTAGE: 1/16W; fp_ECN: 0402 SERIES_LL34.xls
U14 = LM4FB15P9ZADHIN: PROG IC CTRL(212P)XM4E129BNCZADI2(BGA); CLASS: IC; Data: TIC_TM4E129BNCZAD.pdf; From_pj: S1M-MARK; Lifecycle: Comp-Release Qty; MATERIAL: IC; Manuf_name: TEXAS INSTRUMENTS SUPPLY CO.,; Manuftr: TIC; Part_Type: *LF_Chipset; RD_CMPLS_LVL: EP(V1); Standard: Potential
C70 C72 C76 C289 = CAP_NP: CAP CHIP 47P 50V(+-5%.NPO.0402); BOM: AST2300; CLASS: DISCRETE; CMPLS_LVL: EP; Data: AVX_SMCCP.pdf; From_pj: S57-HOWER; Lifecycle: Comp-Approve; MATERIAL: NPO; Manuf_PN: C1005NP0470JGT; Manuf_name: ACER PERIPHERALS INC.(Darfon Electronics Corp.); Manuftr: API; Part_Type: *LF_C0402; Status: Preferred; TOLERANCE: 5%; VOLTAGE: 50V; fp_ECN: 0402 SERIES_LL34.xls
C293 = CAP_NP: CAP CHIP 0.1U 16V(10%.X7R.0402); BOM: AST2300; CLASS: DISCRETE; CMPLS_LVL: EP(V1); Data: MUR_LF_CAP SERIES_1.pdf; FPLIST: C0402,C0402_OCTAGONXA; From_pj: S5A-TRAVIS; Lifecycle: Comp-Approve; MATERIAL: X7R; Manuf_PN: WBM155R71C104K; Manuf_name: MURATA ERIE N.A. INC TAIWAN BRANCH Okayama Murata Mfg.Co..Ltd. Wakura Murata Mfg; Manuftr: MUR; Part_Type: *LF_C0402; RD_CMPLS_LVL: EP(V1); TOLERANCE: 10%; VOLTAGE: 16V; fp_ECN: 0402 SERIES_LL34.xls
R38 = R: RES CHIP 200K 1/16W+-1%(0402); CLASS: DISCRETE; CMPLS_LVL: EP; Data: TAI_LF_RM SERIES-3.pdf; From_pj: RS2-EASON; Lifecycle: Comp-Approve; MATERIAL: CHIP; Manuf_PN: RM04FTN2003; Manuf_name: TA-I TECHNOLOGY CO..LTD.; Manuftr: TAI; Part_Type: *LF_Resistor; TOLERANCE: 1%; WATTAGE: 1/16W; fp_ECN: 0402 SERIES_LL34.xls
R40 R1407 = R: RES CHIP 100K(1/20W,+-5%,0201); CLASS: DISCRETE; CMPLS_LVL: EP(V1); Data: CYN_RL SERIES_revB0.pdf; From_pj: GD1-JOSH; Lifecycle: Comp-Approve; MATERIAL: CHIP; Manuf_PN: RR0306S-104-JN; Manuf_name: CYNTEC CO., LTD.; Manuftr: CYN; Part_Type: *LF_Resistor; RD_CMPLS_LVL: EP(V1); TOLERANCE: 5%; WATTAGE: 1/20W; fp_ECN: DCN-all 0201 RCL part.doc
R56 R70 R517 = R: RESISTOR CHIP 0 1/10W+-5%(0603); CLASS: DISCRETE; CMPLS_LVL: EP; Data: WTC_LF_WR SERIES.pdf; Lifecycle: Comp-Approve; MATERIAL: CHIP; Manuf_PN: CRCW06030000Z0EA; Manuf_name: DALE ELECTRONICS.INC.; Manuftr: DAL; Part_Type: *LF_Resistor; Standard: ##; Status: Normal; TOLERANCE: 5%; WATTAGE: 1/10W
R65 = R: RES CHIP 100K 1/16W +-1% (0402); CLASS: DISCRETE; CMPLS_LVL: EP; Data: WTC_LF_WA06X SERIES.pdf; From_pj: S30-SP; Lifecycle: Comp-Approve; MATERIAL: CHIP; Manuf_PN: RR0510S-104-FN; Manuf_name: CYNTEC CO.. LTD.; Manuftr: CYN; Part_Type: *LF_Resistor; Status: Preferred; TOLERANCE: 1%; WATTAGE: 1/16W; fp_ECN: 0402 SERIES_LL34.xls
R73 R91 R98 = R: RES CHIP 5.11K 1/16W +-1%(0402); BOM: AST2300; CLASS: DISCRETE; CMPLS_LVL: EP; Data: CYN_LF_RL SERIES.pdf; From_pj: RS2-EASON; Lifecycle: Comp-Approve; MATERIAL: CHIP; Manuf_PN: RR0510S-5111-FN; Manuf_name: CYNTEC CO.. LTD.; Manuftr: CYN; Part_Type: *LF_Resistor; Status: Preferred; TOLERANCE: 1%; WATTAGE: 1/16W; fp_ECN: 0402 SERIES_LL34.xls
R78 = R: RES CHIP 1.02K 1/16W +-1%(0402)L-F; BOM: AST2300; CLASS: DISCRETE; Data: CYN_LF_RL SERIES.pdf; From_pj: S76-KEVIN; Lifecycle: Comp-Approve; MATERIAL: CHIP; Manuf_PN: RR0510S-1021-FN; Manuf_name: "CYNTEC CO.. LTD."; Manuftr: CYN; Part_Type: *LF_Resistor; Status: Preferred; TOLERANCE: 1%; WATTAGE: 1/16W; fp_ECN: 0402 SERIES_LL34.xls
R80 = R: RES CHIP 34.8K 1/16W +-1% (0402)EP; CLASS: DISCRETE; CMPLS_LVL: EP; Data: WTC_LF_WR SERIES-3.pdf; From_pj: S90-ALAIN; Lifecycle: Comp-Approve; MATERIAL: CHIP; Manuf_PN: WR04X3482FTL; Manuf_name: WALSIN TECHNOLOGY CORPORATION; Manuftr: WTC; Part_Type: *LF_Resistor; TOLERANCE: 1%; WATTAGE: 1/16W; fp_ECN: 0402 SERIES_LL34.xls
R83 R114 = R: RESISTOR CHIP 8.25K 1/16W+-1%(0402); BOM: AST2300; CLASS: DISCRETE; CMPLS_LVL: EP; Data: YGO_RC0402 SERIES.pdf; From_pj: SJ1-MATT; Lifecycle: Comp-Approve; MATERIAL: CHIP; Manuf_PN: CR028K25F002S; Manuf_name: YAGEO CORPORATION; Manuftr: YGO; Part_Type: *LF_Resistor; Standard: ##; TOLERANCE: 1%; WATTAGE: 1/16W; fp_ECN: 0402 SERIES_LL34.xls
R100 = R: RES CHIP 51.1K 1/16W +-1%(0402) L-F; CLASS: DISCRETE; CMPLS_LVL: EP(V1); Data: TAI_RM04_rev20120619.pdf; From_pj: S76-KEVIN; Lifecycle: Comp-Approve; MATERIAL: CHIP; Manuf_PN: RM04FTN5112; Manuf_name: "TA-I TECHNOLOGY CO..LTD."; Manuftr: TAI; Part_Type: *LF_Resistor; RD_CMPLS_LVL: EP(V1); Status: Preferred; TOLERANCE: 1%; WATTAGE: 1/16W; fp_ECN: 0402 SERIES_LL34.xls
R1408 = R: RESISTOR CHIP 0 1/16W +-5%(0402); CLASS: DISCRETE; CMPLS_LVL: EP; Data: WTC_LF_WR SERIES.pdf; Lifecycle: Comp-Approve; MATERIAL: CHIP; Manuf_PN: RR0510X-000-XN; Manuf_name: CYNTEC CO.. LTD.; Manuftr: CYN; Part_Type: *LF_Resistor; Status: Preferred; TOLERANCE: 5%; WATTAGE: 1/16W; fp_ECN: 0402 SERIES_LL34.xls
U10 = MOSFET_NCH_GDS_ESD_PROTECTED: TRANMOS 2N7002KW SOT323(60V, 115MA,0.2W); CLASS: IC; CMPLS_LVL: EP(V1); Data: PJT_2N7002KW.pdf; From_pj: MF1-EDDIE; Lifecycle: Comp-Approve; MATERIAL: IC; Manuf_name: PAN JIT INTERNATIONAL INC.; Manuftr: PJT; Part_Type: *LF_Semiconductor; RD_CMPLS_LVL: EP(V1); Standard: Standard
U123 = PJC7428: TRANS MOS PJC7428(30V,0.3A,0.35W); CLASS: IC; Data: PJT_PJC7428.pdf; From_pj: XG1-TONY; Lifecycle: P/N Release; MATERIAL: IC; Manuf_name: PAN JIT INTERNATIONAL INC.; Manuftr: PJT; Part_Type: *LF_Semiconductor; RD_CMPLS_LVL: EP(V1)
R427 R462 R464 = R: RES CHIP 33.2 1/16W +-1%(0402); CLASS: DISCRETE; CMPLS_LVL: EP; Data: CYN_LF_RL SERIES.pdf; From_pj: A06-EDISON; Lifecycle: Comp-Approve; MATERIAL: CHIP; Manuf_PN: RR0510S-33R2-FN; Manuf_name: CYNTEC CO.. LTD.; Manufacturer: RHT; Manuftr: CYN; Not_insert: NI; Part_Type: *LF_Resistor; TOLERANCE: 1%; WATTAGE: 1/16W; fp_ECN: 0402 SERIES_LL34.xls; top_bot: TOP
R442 R444 = R: RES CHIP 33.2 1/16W +-1%(0402); CLASS: DISCRETE; CMPLS_LVL: EP; Data: CYN_LF_RL SERIES.pdf; From_pj: A06-EDISON; Lifecycle: Comp-Approve; MATERIAL: CHIP; Manuf_PN: RR0510S-33R2-FN; Manuf_name: CYNTEC CO.. LTD.; Manufacturer: RHT; Manuftr: CYN; Part_Type: *LF_Resistor; TOLERANCE: 1%; WATTAGE: 1/16W; fp_ECN: 0402 SERIES_LL34.xls; top_bot: TOP
R446 = R: RES CHIP 1K 1/16W +-1% (0402); CLASS: DISCRETE; CMPLS_LVL: EP; Data: WTC_LF_WR SERIES.pdf; Lifecycle: Comp-Approve; MATERIAL: CHIP; Manuf_PN: RR0510S-102-FN; Manuf_name: CYNTEC CO.. LTD.; Manufacturer: CYN; Manuftr: CYN; Part_Type: *LF_Resistor; SUBSYS: VR0_RES; Status: Preferred; TOLERANCE: 1%; TOP_BOT: BOT; WATTAGE: 1/16W; fp_ECN: 0402 SERIES_LL34.xls
R449 R455 = R: RES CHIP 10 1/16W +-1%(0402); CLASS: DISCRETE; CMPLS_LVL: EP; Data: TAI_LF_RM SERIES-3.pdf; From_pj: RS2-MATT; MATERIAL: CHIP; Manuf_PN: RM04FTN10R0; Manuf_name: TA-I TECHNOLOGY CO..LTD.; Manuftr: TAI; Part_Type: *LF_Resistor; TOLERANCE: 1%; WATTAGE: 1/16W; fp_ECN: 0402 SERIES_LL34.xls
R450 R451 = R: RES CHIP 240 1/16W +-5%(0402); CLASS: DISCRETE; CMPLS_LVL: EP; Data: YGO_RC0402 SERIES.pdf; From_pj: TU1B-MARTIN; Lifecycle: Comp-Approve; MATERIAL: CHIP; Manuf_PN: RC0402JR-07240RL; Manuf_name: YAGEO CORPORATION; Manufacturer: TAI; Manuftr: YGO; Part_Type: *LF_Resistor; RD_CMPLS_LVL: EP; TOLERANCE: 5%; WATTAGE: 1/16W; fp_ECN: 0402 SERIES_LL34.xls
R457 R459 R1365 = R: RES CHIP 2.21K 1/16W +-1% (0402); CLASS: DISCRETE; CMPLS_LVL: EP; Data: WTC_LF_WR SERIES-4.pdf; From_pj: TU1-SUNGHSIN; Lifecycle: Comp-Approve; MATERIAL: CHIP; Manuf_PN: WR04X2211FTL; Manuf_name: WALSIN TECHNOLOGY CORPORATION; Manuftr: WTC; Part_Type: *LF_Resistor; TOLERANCE: 1%; WATTAGE: 1/16W; fp_ECN: 0402 SERIES_LL34.xls
U4 U58 U62 = PCA9617DP: IC OTHER(8P) PCA9617ADP(TSSOP); CLASS: IC; CMPLS_LVL: EP(V1); Data: NXP_PCA9617A.pdf; From_pj: S1U-OWEN; Lifecycle: Comp-Approve; MATERIAL: IC; Manuf_name: NXP semiconductors; Manuftr: NXP; Part_Type: *LF_Chipset; RD_CMPLS_LVL: EP(V1); Standard: Potential
C608 = CAP_NP: CAP CHIP 0.1U 25V(+-10%,X7R,0402); CLASS: DISCRETE; Data: YGO_CA-CC-SC SERIES.pdf; From_pj: F03-KC; Lifecycle: Comp-Approve; MATERIAL: X7R; Manuf_PN: CC0402KRX7R8BB104; Manuf_name: YAGEO CORPORATION; Manuftr: YGO; Part_Type: *LF_C0402; RD_CMPLS_LVL: EP(V1); Standard: End of Design; TOLERANCE: 10%; VOLTAGE: 25V; fp_ECN: 0402 SERIES_LL34.xls
D3-D10 D14-D17 = LED2P_AC: LED SMD(2P)YELL/GRE(27-21/G6C-AN2Q1B/3C; CLASS: IC; CMPLS_LVL: EP(V1); Data: EVL_27-21G6C-AN2Q1B3C.pdf; From_pj: T20-TONY; Lifecycle: Comp-Approve; MATERIAL: IC; Manuf_PN: 27-21/G6C-AN2Q1B/3C; Manuf_name: EVERLIGHT (EVERLIGHT ELECTRONICS CO., LTD. ); Manuftr: EVL; Part_Type: *LF_Semiconductor; RD_CMPLS_LVL: EP(V1)
D12 = LED2P_AC: LED SMD(2P)BLUE(27-21/BHC-ZM2N2TY/3C); CLASS: IC; CMPLS_LVL: EP(V1); Data: EVL_27-21BHC-ZM2N2TY3C.pdf; From_pj: T6MB-TONY; Lifecycle: Comp-Approve; MATERIAL: IC; Manuf_PN: 27-21/BHC-ZM2N2TY/3C; Manuf_name: EVERLIGHT (EVERLIGHT ELECTRONICS CO., LTD. ); Manuftr: EVL; Part_Type: *LF_Semiconductor; RD_CMPLS_LVL: EP(V1)
Q7 Q8 = MOSFET_DUAL_6P: TRANS MOS 2N7002KDW(60V115MA,0.2W)SOT363; CLASS: IC; CMPLS_LVL: EP(V1); Data: PJT_2N7002KDW.pdf; From_pj: F06S-KENG-YU; Lifecycle: Comp-Approve; MATERIAL: IC; Manuf_name: PAN JIT INTERNATIONAL INC.; Manuftr: PJT; Part_Type: *LF_Semiconductor; RD_CMPLS_LVL: EP(V1)
R151 R154 R157 R164 R169 R558 R566 R569 R802-R805 = R: RES CHIP 220 1/16W +-1%(0402); CLASS: DISCRETE; CMPLS_LVL: EP; Data: TAI_LF_RM SERIES-2.pdf; From_pj: S2F-JOSEPH; Lifecycle: Comp-Approve; MATERIAL: CHIP; Manuf_PN: RM04FTN2200; Manuf_name: TA-I TECHNOLOGY CO..LTD.; Manufacturer: CYN; Manuftr: TAI; Part_Type: *LF_Resistor; TOLERANCE: 1%; WATTAGE: 1/16W; fp_ECN: 0402 SERIES_LL34.xls; top_bot: TOP
R461 = R: RES CHIP 470 1/16W +-1%(0402); CLASS: DISCRETE; CMPLS_LVL: EP(V1); Data: CYN_R SERIES_REVA0.pdf; From_pj: S2BP-PH; Lifecycle: Comp-Approve; MATERIAL: CHIP; Manuf_PN: RR0510S-471-FN; Manuf_name: CYNTEC CO.. LTD.; Manufacturer: CYN; Manuftr: CYN; Part_Type: *LF_Resistor; RD_CMPLS_LVL: EP(V1); TOLERANCE: 1%; WATTAGE: 1/16W; fp_ECN: 0402 SERIES_LL34.xls; top_bot: TOP
U6 = SN74LVC1G07: IC OTHER(5P)SN74LVC1G07DCKR(SOT); CLASS: IC; CMPLS_LVL: EP(V1); Data: TIC_SN74LVC1G07DCKR.pdf; From_pj: S50-STEVE; Lifecycle: Comp-Approve; MATERIAL: IC; Manuf_name: TEXAS INSTRUMENTS SUPPLY CO..; Manuftr: TIC; Part_Type: *LF_Chipset; RD_CMPLS_LVL: EP(V1); Standard: Potential
J44-J71 J76-J79 J96-J103 = PICOPROBE_B: Probe for DELTA-L measurement; CLASS: IO; DIP_SMD: DIP; Data: Delta-L New symbol.msg; MATERIAL: MISC; Part_Type: *LF_Misc; fp_ECN: TRIANG_LAUNCH_3PXA.pdf
J80-J95 J104-J107 = TDR_3P_TH2: TDR 3PIN,2X141MIL 1X100MIL P2P; CLASS: IO; Data: TDR_3P_C85P67_141_100M_Q.msg; From_pj: F09-MARK; MATERIAL: MISC; Part_Type: *LF_Misc
X1-X40 = TP_TDR_4P_FTS: DIFF_TEST_PAD DIP FOR FTS ONLY; CLASS: IO; DIP_SMD: DIP; From_pj: TU1B-MICHAEL; MATERIAL: MISC; Part_Type: MISC
C93 = CAP_NP: CAP CHIP 1UF 25V(+-10%,X6S,0402); CLASS: DISCRETE; CMPLS_LVL: EP(V1); Data: MUR_GRM155R72A221KA01-01.pdf; From_pj: F06-RAYMOND; Lifecycle: Comp-Approve; MATERIAL: X6S; Manuf_PN: GRM155C81E105K; Manuf_name: MURATA ERIE N.A. INC TAIWAN BRANCH Okayama Murata Mfg.Co..Ltd.Wakura Murata Mfg.; Manuftr: MUR; Part_Type: *LF_C0402; RD_CMPLS_LVL: EP(V1); TOLERANCE: 10%; VOLTAGE: 25V; fp_ECN: 0402 SERIES_LL34.xls
Q6 = MBT3904DW1T1: TRANSISTOR SMD MMDT3904-7-F(40V.200MA); CLASS: IC; CMPLS_LVL: EP(V1); Data: DDS_MMDT3904-7-F.pdf; From_pj: S50-STEVE; Lifecycle: Comp-Approve; MATERIAL: IC; Manuf_PN: MMDT3904-7-F; Manuf_name: DIODES TAIWAN CO..LTD.(Kai Hong Shanghai); Manuftr: DDS; Part_Type: *LF_Semiconductor; RD_CMPLS_LVL: EP(V1)
R661 = R: RES CHIP 4.7K 1/16W +-5% (0402); CLASS: DISCRETE; CMPLS_LVL: EP; Data: WTC_LF_WR SERIES.pdf; Lifecycle: Comp-Approve; MATERIAL: CHIP; Manuf_PN: RR0510S-472-JN; Manuf_name: CYNTEC CO.. LTD.; Manufacturer: RLC; Manuftr: CYN; Part_Type: *LF_Resistor; Status: Preferred; TOLERANCE: 5%; WATTAGE: 1/16W; fp_ECN: 0402 SERIES_LL34.xls; top_bot: TOP
R708 = R: RES CHIP 1.5K 1/16W +-5%(0402)EP; CLASS: DISCRETE; CMPLS_LVL: EP; Data: TAI_LF_RM SERIES-2.pdf; From_pj: S75-LA; MATERIAL: CHIP; Manuf_PN: RM04JTN152; Manuf_name: TA-I TECHNOLOGY CO..LTD.; Manufacturer: RLC; Manuftr: TAI; Part_Type: *LF_Resistor; Status: Preferred; TOLERANCE: 5%; WATTAGE: 1/16W; fp_ECN: 0402 SERIES_LL34.xls; top_bot: TOP
R716 = R: RES CHIP 1K 1/16W +-1% (0402); CLASS: DISCRETE; CMPLS_LVL: EP; Data: WTC_LF_WR SERIES.pdf; Lifecycle: Comp-Approve; MATERIAL: CHIP; Manuf_PN: RR0510S-102-FN; Manuf_name: CYNTEC CO.. LTD.; Manufacturer: RLC; Manuftr: CYN; Part_Type: *LF_Resistor; Status: Preferred; TOLERANCE: 1%; WATTAGE: 1/16W; fp_ECN: 0402 SERIES_LL34.xls; top_bot: TOP
R1150 = R: RES CHIP 33.2 1/16W +-1%(0402); CLASS: DISCRETE; CMPLS_LVL: EP; Data: CYN_LF_RL SERIES.pdf; From_pj: A06-EDISON; Lifecycle: Comp-Approve; MATERIAL: CHIP; Manuf_PN: RR0510S-33R2-FN; Manuf_name: CYNTEC CO.. LTD.; Manuftr: CYN; Part_Type: *LF_Resistor; TOLERANCE: 1%; WATTAGE: 1/16W; fp_ECN: 0402 SERIES_LL34.xls
U34 = ADM803RAKS-REEL7: IC OTHER (3P) MAX803TEXR+T(SC70); CLASS: IC; CMPLS_LVL: EP(V1); Data: MAX803-809-810.pdf; From_pj: T2M-MARK; Lifecycle: Comp-Approve; MATERIAL: IC; Manuf_name: MAXIM JAPAN CO.,LTD(DALLAS SEMICONDUCTOR CORP.); Manuftr: MAM; Part_Type: *LF_Chipset; RD_CMPLS_LVL: EP(V1)

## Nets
GND: C70.2 C72.2 C76.2 C93.2 C154.1 C155.1 C156.1 C158.1 C168.2 C200.1 C224.1 C229.2 C245.2 C248.1 C256.2 C258.2 C259.2 C263.2 C264.2 C265.2 C266.2 C267.2 C268.2 C269.2 C271.2 C272.2 C273.2 C275.2 C278.2 C280.2 C289.2 C293.2 C294.2 C295.2 C308.2 C462.2 C608.2 Q6.1(E) Q6.4(E) Q7.1(S1) Q7.4(S2) Q8.1(S1) Q8.4(S2) R40.2 R65.2 R78.2 R80.2 R83.2 R114.2 R1307.1 R1309.1 R1407.2 U4.4(GND) U6.3(GND) U14.A1(GND21) U14.A2(GND24) U14.A18(GND22) U14.A19(GND23) U14.B1(GND25) U14.B19(GND26) U14.F10(GND15) U14.G4(GNDA) U14.H10(GND18) U14.H11(GND19) U14.H12(GND20) U14.J11(GND16) U14.J12(GND17) U14.K6(GND13) U14.K9(GND14) U14.K10(GND10) U14.K13(GND11) U14.K14(GND12) U14.L8(GND1) U14.L9(GND2) U14.M8(GND3) U14.M9(GND4) U14.M10(GND9) U14.N10(GND5) U14.P16(GND27) U14.R17(GND28) U14.V1(GND6) U14.W1(GND7) U14.W2(GND8) U34.1(GND) U47.4(GND) U52.2(GND) U54.1(1OE_N) U54.4(1DIR) U54.5(2DIR) U54.10(GND_1) U54.11(GND_2) U54.16(2OE_N) U58.4(GND) U62.4(GND) ; also on sheet 1 2 3 4 11 12 13 14 15 16 17 18 19 20 22 23 24 25 26 27 28 31 32 41 42 45 46 47 48 49 50 51 52 53 54 55 56 57 58 59 60 61 62 63 64 65 66 67 68 69 70 71 72 82 83 84 86 87 88 92
GND1: J44.3 J45.3 J46.3 J47.3 J48.3 J49.3 J50.3 J51.3 J52.3 J53.3 J54.3 J55.3 J56.3 J57.3 J58.3 J59.3 J60.3 J61.3 J62.3 J63.3 J64.3 J65.3 J66.3 J67.3 J68.3 J69.3 J70.3 J71.3 J76.3 J77.3 J78.3 J79.3 J96.3 J97.3 J98.3 J99.3 J100.3 J101.3 J102.3 J103.3
GND2: J80.1(GND) J81.1(GND) J82.1(GND) J83.1(GND) J84.1(GND) J85.1(GND) J86.1(GND) J87.1(GND) J88.1(GND) J89.1(GND) J90.1(GND) J91.1(GND) J92.1(GND) J93.1(GND) J94.1(GND) J95.1(GND) J104.1(GND) J105.1(GND) J106.1(GND) J107.1(GND) X1.2(P1) X1.3(P2) X2.2(P1) X2.3(P2) X3.2(P1) X3.3(P2) X4.2(P1) X4.3(P2) X5.2(P1) X5.3(P2) X6.2(P1) X6.3(P2) X7.2(P1) X7.3(P2) X8.2(P1) X8.3(P2) X9.2(P1) X9.3(P2) X10.2(P1) X10.3(P2) X11.2(P1) X11.3(P2) X12.2(P1) X12.3(P2) X13.2(P1) X13.3(P2) X14.2(P1) X14.3(P2) X15.2(P1) X15.3(P2) X16.2(P1) X16.3(P2) X17.2(P1) X17.3(P2) X18.2(P1) X18.3(P2) X19.2(P1) X19.3(P2) X20.2(P1) X20.3(P2) X21.2(P1) X21.3(P2) X22.2(P1) X22.3(P2) X23.2(P1) X23.3(P2) X24.2(P1) X24.3(P2) X25.2(P1) X25.3(P2) X26.2(P1) X26.3(P2) X27.2(P1) X27.3(P2) X28.2(P1) X28.3(P2) X29.2(P1) X29.3(P2) X30.2(P1) X30.3(P2) X31.2(P1) X31.3(P2) X32.2(P1) X32.3(P2) X33.2(P1) X33.3(P2) X34.2(P1) X34.3(P2) X35.2(P1) X35.3(P2) X36.2(P1) X36.3(P2) X37.2(P1) X37.3(P2) X38.2(P1) X38.3(P2) X39.2(P1) X39.3(P2) X40.2(P1) X40.3(P2)
P1V05_COMBINED: C156.2 C158.2 C200.2 C224.2 C248.2 R56.1 R413.1 R450.1 R451.1 U4.1(VCCA) U52.6(VCC_B) U54.2(VCC_B) U58.1(VCCA) U62.1(VCCA) ; also on sheet 1 3 4 16 18 19 41 42 45 47 48 50 51 52 54 55 56 63 71 84 92 94
P1V05_COMBINED_AST_SCALED: C70.1 R56.2 ; also on sheet 71
P1V05_PCH: R70.1 ; also on sheet 50 51 52 63 67 84
P1V05_PCH_AST_SCALED: C76.1 R70.2 ; also on sheet 71
P2V5_VPP: C229.1 R441.2 R443.2 R446.2 U4.8(VCCB) ; also on sheet 11 15 19 25 60 61
P3V3: D3.A D4.A D5.A D6.A D7.A D8.A D9.A D10.A R73.1 R716.2 ; also on sheet 4 19 20 32 41 42 46 47 49 50 52 55 56 63 67
P3V3_AST_SCALED: C295.1 R73.2 R83.1 ; also on sheet 71
P3V3_STBY: C93.1 C154.2 C155.2 C168.1 C245.1 C264.1 C265.1 C266.1 C267.1 C268.1 C269.1 C271.1 C272.1 C273.1 C275.1 C278.1 C280.1 C462.1 C608.1 D12.A R21.1 R91.1 R95.1 R99.1 R192.1 R232.1 R378.1 R457.2 R459.2 R479.1 R480.1 R508.1 R510.1 R511.1 R514.1 R632.1 R661.2 R682.2 R702.1 R802.2 R803.2 R804.2 R805.2 R1199.1 R1200.1 R1306.1 R1308.1 R1365.2 R1398.1 U6.5(VCC) U14.F3(VDDA) U14.G10(VDD13) U14.H9(VDD14) U14.J8(VDD3) U14.J9(VDD4) U14.J10(VDD15) U14.K7(VDD11) U14.K8(VDD12) U14.K11(VDD9) U14.K12(VDD10) U14.L10(VDD1) U14.L11(VDD2) U14.L12(VDD5) U14.M11(VDD6) U14.M12(VDD7) U14.N16(VDD17) U14.P10(VDD8) U14.P17(VDD16) U34.3(VCC) U47.8(VCC) U52.1(VCC_A) U52.5(DIR) U54.3(VCC_A) U58.8(VCCB) U62.8(VCCB) ; also on sheet 3 4 13 14 16 18 19 20 22 24 25 26 27 28 31 32 41 52 55 56 57 58 59 62 63 64 65 67 68 69 70 71 72 82 84 86 87 88 92
P3V3_STBY_AST_SCALED: C308.1 R91.2 R114.1 ; also on sheet 71
P3V_BAT_AST_SCALED: C72.1 R65.1 U10.S ; also on sheet 71
P3V_BAT_R: R38.1 ; also on sheet 18
P3V_BAT_R1: R38.2 U10.D
P5V_STBY: R1408.1 ; also on sheet 1 2 13 23 26 31 70 84
P5V_STBY_AST_SCALED: C293.1 R80.1 U123.S ; also on sheet 71
P5V_STBY_DETECT: R1407.1 U123.G ; also on sheet 71
P5V_STBY_R: R100.1 R1408.2
P5V_STBY_R1: R100.2 U123.D
P12V_AST_SCALED: C294.1 R78.1 R98.2 ; also on sheet 71
P12V_STBY: R98.1 ; also on sheet 2 3 23 24 25 27 28 86
PVDDRA_AST_SCALED: C289.1 R517.2 ; also on sheet 71
VDDC_OUTPUT: C256.1 C258.1 C259.1 C263.1 U14.E10(VDDC2) U14.H16(VDDC1)
BATTERY_DETECT: R40.1 U10.G ; also on sheet 71
BMC_RST_BTN_OUT_N: R192.2 R708.1 ; also on sheet 71
BMC_RST_BTN_OUT_R_N: Q6.2(B) R708.2
DELTA_L_BOT_5IN_85OHM_DN: J76.1 J77.2
DELTA_L_BOT_5IN_85OHM_DP: J76.2 J77.1
DELTA_L_BOT_10IN_85OHM_DN: J78.2 J79.1
DELTA_L_BOT_10IN_85OHM_DP: J78.1 J79.2
DELTA_L_IN1_5IN_85OHM_DN: J48.1 J49.2
DELTA_L_IN1_5IN_85OHM_DP: J48.2 J49.1
DELTA_L_IN1_10IN_85OHM_DN: J50.1 J51.2
DELTA_L_IN1_10IN_85OHM_DP: J50.2 J51.1
DELTA_L_IN2_5IN_85OHM_DN: J52.1 J53.2
DELTA_L_IN2_5IN_85OHM_DP: J52.2 J53.1
DELTA_L_IN2_10IN_85OHM_DN: J54.1 J55.2
DELTA_L_IN2_10IN_85OHM_DP: J54.2 J55.1
DELTA_L_IN3_5IN_85OHM_DN: J56.1 J57.2
DELTA_L_IN3_5IN_85OHM_DP: J56.2 J57.1
DELTA_L_IN3_10IN_85OHM_DN: J58.2 J59.1
DELTA_L_IN3_10IN_85OHM_DP: J58.1 J59.2
DELTA_L_IN4_5IN_85OHM_DN: J60.1 J61.2
DELTA_L_IN4_5IN_85OHM_DP: J60.2 J61.1
DELTA_L_IN4_10IN_85OHM_DN: J62.1 J63.2
DELTA_L_IN4_10IN_85OHM_DP: J62.2 J63.1
DELTA_L_IN5_5IN_85OHM_DN: J64.1 J65.2
DELTA_L_IN5_5IN_85OHM_DP: J64.2 J65.1
DELTA_L_IN5_10IN_85OHM_DN: J66.1 J67.2
DELTA_L_IN5_10IN_85OHM_DP: J66.2 J67.1
DELTA_L_IN6_5IN_85OHM_DN: J68.1 J69.2
DELTA_L_IN6_5IN_85OHM_DP: J68.2 J69.1
DELTA_L_IN6_10IN_85OHM_DN: J70.1 J71.2
DELTA_L_IN6_10IN_85OHM_DP: J70.2 J71.1
DELTA_L_IN7_5IN_85OHM_DN: J96.1 J97.2
DELTA_L_IN7_5IN_85OHM_DP: J96.2 J97.1
DELTA_L_IN7_10IN_85OHM_DN: J98.1 J99.2
DELTA_L_IN7_10IN_85OHM_DP: J98.2 J99.1
DELTA_L_IN8_5IN_85OHM_DN: J100.1 J101.2
DELTA_L_IN8_5IN_85OHM_DP: J100.2 J101.1
DELTA_L_IN8_10IN_85OHM_DN: J102.1 J103.2
DELTA_L_IN8_10IN_85OHM_DP: J102.2 J103.1
DELTA_L_TOP_5IN_85OHM_DN: J44.1 J45.2
DELTA_L_TOP_5IN_85OHM_DP: J44.2 J45.1
DELTA_L_TOP_10IN_85OHM_DN: J46.1 J47.2
DELTA_L_TOP_10IN_85OHM_DP: J46.2 J47.1
FM_CPLD_RSMRST_N: R1150.2 ; also on sheet 64
FM_CPLD_RSMRST_N_R: R232.2 R1150.1 U34.2(~{RESET})
FM_PWR_LED_N: R21.2 U6.2(A) ; also on sheet 72
FM_PWR_LED_R_N: R461.2 U6.4(Y)
FP_PWR_BTN_BUF_N: R632.2 ; also on sheet 64 69 72
LED_CPLD_D1: Q7.2(G1) ; also on sheet 64
LED_CPLD_D1_GREEN: D14.C Q7.6(D1)
LED_CPLD_D1_GREEN_R: D14.A R802.1
LED_CPLD_D2: Q7.5(G2) ; also on sheet 14
LED_CPLD_D2_GREEN: D15.C Q7.3(D2)
LED_CPLD_D2_GREEN_R: D15.A R803.1
LED_CPLD_D3: Q8.2(G1) ; also on sheet 14
LED_CPLD_D3_GREEN: D16.C Q8.6(D1)
LED_CPLD_D3_GREEN_R: D16.A R804.1
LED_CPLD_D4: Q8.5(G2) ; also on sheet 14
LED_CPLD_D4_GREEN: D17.C Q8.3(D2)
LED_CPLD_D4_GREEN_R: D17.A R805.1
PCA9617_U58_EN: R1308.2 R1309.2 U58.5(EN)
PCA9617_U62_EN: R1306.2 R1307.2 U62.5(EN)
PORT80_LED0: R169.1 ; also on sheet 71
PORT80_LED0_R: D4.C R169.2
PORT80_LED1: R566.1 ; also on sheet 71
PORT80_LED1_R: D6.C R566.2
PORT80_LED2: R157.1 ; also on sheet 71
PORT80_LED2_R: D8.C R157.2
PORT80_LED3: R164.1 ; also on sheet 71
PORT80_LED3_R: D10.C R164.2
PORT80_LED4: R558.1 ; also on sheet 71
PORT80_LED4_R: D3.C R558.2
PORT80_LED5: R151.1 ; also on sheet 71
PORT80_LED5_R: D5.C R151.2
PORT80_LED6: R154.1 ; also on sheet 72
PORT80_LED6_R: D7.C R154.2
PORT80_LED7: R569.1 ; also on sheet 72
PORT80_LED7_R: D9.C R569.2
PU_PCA9617_ENABLE: R446.1 U4.5(EN)
PV_VDDRAB: R517.1 ; also on sheet 11 15 22 23 24 51 60 61
PWR_LED_BLUE_R: D12.C R461.1
RST_PCH_SYS_RESET_N: Q6.3(C) R716.1 ; also on sheet 47
RST_PCH_SYS_RESET_R: Q6.5(B) Q6.6(C) R661.1
SMB_BMC_3V3SB_ALRT_N: R1398.2 ; also on sheet 13 71
SMB_BMC_3V3SB_CLK: R99.2 R1205.1 ; also on sheet 65
SMB_BMC_3V3SB_CLK_R: R1205.2 ; also on sheet 71
SMB_BMC_3V3SB_DAT: R95.2 R1206.1 ; also on sheet 65
SMB_BMC_3V3SB_DAT_R: R1206.2 ; also on sheet 71
SMB_DDR01_CLK: R449.1 ; also on sheet 18
SMB_DDR01_DAT: R455.1 ; also on sheet 18
SMB_HOST_2V5_CLK_D38: R443.1 R444.1 U4.7(SCLB)
SMB_HOST_2V5_CLK_R3: R444.2 ; also on sheet 60 61
SMB_HOST_2V5_DAT_D38: R441.1 R442.1 U4.6(SDAB)
SMB_HOST_2V5_DAT_R3: R442.2 ; also on sheet 60 61
SMB_HOST_3V3SB_CLK: R109.2 R479.2 ; also on sheet 71
SMB_HOST_3V3SB_DAT: R480.2 R529.2 ; also on sheet 71
SMB_HOST_XDP_CLK: R1200.2 ; also on sheet 18 54 62 71
SMB_HOST_XDP_DAT: R1199.2 ; also on sheet 18 54 62 71
SMB_LAN_3V3SB_ALRT_N: R427.2 ; also on sheet 87
SMB_LAN_3V3SB_ALRT_R_N: R427.1 R1365.1 U58.7(SCLB)
SMB_LAN_3V3SB_CLK: R464.2 ; also on sheet 87
SMB_LAN_3V3SB_CLK_R: R459.1 R464.1 U62.7(SCLB)
SMB_LAN_3V3SB_DAT: R462.2 ; also on sheet 87
SMB_LAN_3V3SB_DAT_R: R457.1 R462.1 U62.6(SDAB)
SMB_LAN_ALRT_N: U58.2(SCLA) ; also on sheet 45
SMB_LAN_CLK: U62.2(SCLA) ; also on sheet 45
SMB_LAN_DAT: U62.3(SDAA) ; also on sheet 45
SMB_PCA9617_CLK_R: R449.2 R450.2 U4.2(SCLA)
SMB_PCA9617_DAT_R: R451.2 R455.2 U4.3(SDAA)
SMB_SENSOR_3V3SB_CLK: R510.2 R1197.1 R1437.2 ; also on sheet 68
SMB_SENSOR_3V3SB_CLK_R: R1197.2 ; also on sheet 71
SMB_SENSOR_3V3SB_CLK_R1: R1437.1 ; also on sheet 68
SMB_SENSOR_3V3SB_DAT: R508.2 R1198.1 R1436.2 ; also on sheet 68
SMB_SENSOR_3V3SB_DAT_R: R1198.2 ; also on sheet 71
SMB_SENSOR_3V3SB_DAT_R1: R1436.1 ; also on sheet 68
SMB_SML0_3V3SB_CLK: R511.2 R1201.1 ; also on sheet 18
SMB_SML0_3V3SB_CLK_R: R1201.2 ; also on sheet 71
SMB_SML0_3V3SB_DAT: R514.2 R1202.1 ; also on sheet 18
SMB_SML0_3V3SB_DAT_R: R1202.2 ; also on sheet 71
SMB_VR12_SCL: R109.1 R1434.2 ; also on sheet 3
SMB_VR12_SCL_RR: R1434.1 ; also on sheet 3 24
SMB_VR12_SDA: R529.1 R1435.2 ; also on sheet 3
SMB_VR12_SDA_RR: R1435.1 ; also on sheet 3 24
SPI_10GBE_CLK: U54.12(2B2) ; also on sheet 45
SPI_10GBE_CLK_LVC3V3: R383.2 U54.9(2A2)
SPI_10GBE_CLK_LVC3V3_R: R383.1 U47.6(CLK)
SPI_10GBE_CS_N: R413.2 U54.15(1B1) ; also on sheet 45
SPI_10GBE_CS_N_LVC3V3: R385.2 U54.6(1A1)
SPI_10GBE_CS_N_LVC3V3_R: R385.1 R702.2 U47.1(CS#)
SPI_10GBE_MISO: R397.2 ; also on sheet 45
SPI_10GBE_MISO_LVC3V3: R376.1 U52.3(A)
SPI_10GBE_MISO_LVC3V3_R: R376.2 U47.2(DO)
SPI_10GBE_MISO_R: R397.1 U52.4(B)
SPI_10GBE_MOSI: U54.14(1B2) ; also on sheet 45
SPI_10GBE_MOSI_LVC3V3: R384.2 U54.7(1A2)
SPI_10GBE_MOSI_LVC3V3_R: R384.1 U47.5(DI)
SPI_NIC_EEPROM_HOLD_N: R682.1 U47.7(HOLD#||RESET#)
SPI_NIC_EEPROM_WP_N: R378.2 U47.3(WP#)
TDR_DIFF_85_BOT_DIN: X7.4(S2) X8.1(S1)
TDR_DIFF_85_BOT_DIP: X7.1(S1) X8.4(S2)
TDR_DIFF_85_IN1_DIN: X9.4(S2) X10.1(S1)
TDR_DIFF_85_IN1_DIP: X9.1(S1) X10.4(S2)
TDR_DIFF_85_IN2_DIN: X11.4(S2) X12.1(S1)
TDR_DIFF_85_IN2_DIP: X11.1(S1) X12.4(S2)
TDR_DIFF_85_IN3_DIN: X13.4(S2) X14.1(S1)
TDR_DIFF_85_IN3_DIP: X13.1(S1) X14.4(S2)
TDR_DIFF_85_IN4_DIN: X15.4(S2) X16.1(S1)
TDR_DIFF_85_IN4_DIP: X15.1(S1) X16.4(S2)
TDR_DIFF_85_IN5_DIN: X17.4(S2) X18.1(S1)
TDR_DIFF_85_IN5_DIP: X17.1(S1) X18.4(S2)
TDR_DIFF_85_IN6_DIN: X19.4(S2) X20.1(S1)
TDR_DIFF_85_IN6_DIP: X19.1(S1) X20.4(S2)
TDR_DIFF_85_IN7_DIN: X34.1(S1) X35.4(S2)
TDR_DIFF_85_IN7_DIP: X34.4(S2) X35.1(S1)
TDR_DIFF_85_IN8_DIN: X33.1(S1) X36.4(S2)
TDR_DIFF_85_IN8_DIP: X33.4(S2) X36.1(S1)
TDR_DIFF_85_TOP_DIN: X5.4(S2) X6.1(S1)
TDR_DIFF_85_TOP_DIP: X5.1(S1) X6.4(S2)
TDR_DIFF_100_BOT_DIN: X3.4(S2) X4.1(S1)
TDR_DIFF_100_BOT_DIP: X3.1(S1) X4.4(S2)
TDR_DIFF_100_IN1_DIN: X21.1(S1) X22.4(S2)
TDR_DIFF_100_IN1_DIP: X21.4(S2) X22.1(S1)
TDR_DIFF_100_IN2_DIN: X23.1(S1) X24.4(S2)
TDR_DIFF_100_IN2_DIP: X23.4(S2) X24.1(S1)
TDR_DIFF_100_IN3_DIN: X25.1(S1) X26.4(S2)
TDR_DIFF_100_IN3_DIP: X25.4(S2) X26.1(S1)
TDR_DIFF_100_IN4_DIN: X27.1(S1) X28.4(S2)
TDR_DIFF_100_IN4_DIP: X27.4(S2) X28.1(S1)
TDR_DIFF_100_IN5_DIN: X29.1(S1) X30.4(S2)
TDR_DIFF_100_IN5_DIP: X29.4(S2) X30.1(S1)
TDR_DIFF_100_IN6_DIN: X31.1(S1) X32.4(S2)
TDR_DIFF_100_IN6_DIP: X31.4(S2) X32.1(S1)
TDR_DIFF_100_IN7_DIN: X37.1(S1) X38.4(S2)
TDR_DIFF_100_IN7_DIP: X37.4(S2) X38.1(S1)
TDR_DIFF_100_IN8_DIN: X39.1(S1) X40.4(S2)
TDR_DIFF_100_IN8_DIP: X39.4(S2) X40.1(S1)
TDR_DIFF_100_TOP_DIN: X1.4(S2) X2.1(S1)
TDR_DIFF_100_TOP_DIP: X1.1(S1) X2.4(S2)
TDR_SE_40_OHM_BOT: J94.2(IO1) J94.3(IO2)
TDR_SE_40_OHM_IN1: J82.2(IO1) J82.3(IO2)
TDR_SE_40_OHM_IN2: J84.2(IO1) J84.3(IO2)
TDR_SE_40_OHM_IN3: J86.2(IO1) J86.3(IO2)
TDR_SE_40_OHM_IN4: J88.2(IO1) J88.3(IO2)
TDR_SE_40_OHM_IN5: J90.2(IO1) J90.3(IO2)
TDR_SE_40_OHM_IN6: J92.2(IO1) J92.3(IO2)
TDR_SE_40_OHM_IN7: J104.2(IO1) J104.3(IO2)
TDR_SE_40_OHM_IN8: J106.2(IO1) J106.3(IO2)
TDR_SE_40_OHM_TOP: J80.2(IO1) J80.3(IO2)
TDR_SE_50_OHM_BOT: J95.2(IO1) J95.3(IO2)
TDR_SE_50_OHM_IN1: J83.2(IO1) J83.3(IO2)
TDR_SE_50_OHM_IN2: J85.2(IO1) J85.3(IO2)
TDR_SE_50_OHM_IN3: J87.2(IO1) J87.3(IO2)
TDR_SE_50_OHM_IN4: J89.2(IO1) J89.3(IO2)
TDR_SE_50_OHM_IN5: J91.2(IO1) J91.3(IO2)
TDR_SE_50_OHM_IN6: J93.2(IO1) J93.3(IO2)
TDR_SE_50_OHM_IN7: J105.2(IO1) J105.3(IO2)
TDR_SE_50_OHM_IN8: J107.2(IO1) J107.3(IO2)
TDR_SE_50_OHM_TOP: J81.2(IO1) J81.3(IO2)
TP_PCA9617_U137_SDAA: U58.3(SDAA)
TP_PCA9617_U137_SDAB: U58.6(SDAB)

Not connected (* = marked no-connect by the designer): U6 1(NC)*; U14 C5(NC6)* E13(NC5)* V13(NC8)* V14(NC10)* V15(NC11)* V18(NC1)* V19(NC2)* W13(NC9)* W15(NC7)* W18(NC3)* W19(NC4)*; U54 8(2A1)* 13(2B1)*

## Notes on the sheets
sheet 73
- SNOWFLAKE_3
sheet 74
- AVIN_4
- AVIN_0
- AVIN_5
- AVIN_1
- AVIN_6
- AVIN_2
- AVIN_3
- AVIN_7
- VOLTAGE MONITOR
sheet 75
- DESIGN NOTE : VIH Min is 0.7 * VCCB. And EN has intrnal PU to VCCB.
- SMBUS ISOLATOR
sheet 76
- TDR-DIFFERENTIAL
- DELTA-L
- IN7
- IN7
- IN8
- IN8
- IN7
- TDR-SINGLE
- IN7
- IN8
- IN8
- DELTA-L AND TDR_3
sheet 77
- PORT 80(LED only)
- POWER LED
  (BLUE)
- PWR/ PORT 80 LED
sheet 78
- DELTA-L
- IN2
- IN5
- TOP
- IN3
- IN6
- IN1
- IN4
- BOT
- IN2
- IN5
- TDR-SINGLE
- IN3
- TOP
- IN6
- IN1
- IN4
- DELTA-L AND TDR_1
sheet 79
- BDX-DE 10GBE LAN_2
sheet 80
- TDR-SINGLE
- IN3
- IN1
- BOT
- IN2
- IN4
- IN3
- TDR-DIFFERENTIAL
- IN5
- IN4
- TOP
- IN6
- BOT
- IN5
- TOP
- IN1
- IN6
- BOT
- IN2
- DELTA-L AND TDR_2
sheet 81
- RSMRST_N
- SYS RESET
- RSMRST
